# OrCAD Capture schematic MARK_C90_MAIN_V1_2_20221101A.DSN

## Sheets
1 PAGE08_USB_WIFI: size A3; title: MARK_C90_MAIN; rev: V1.2; note: PAGE08_USB-WIFI
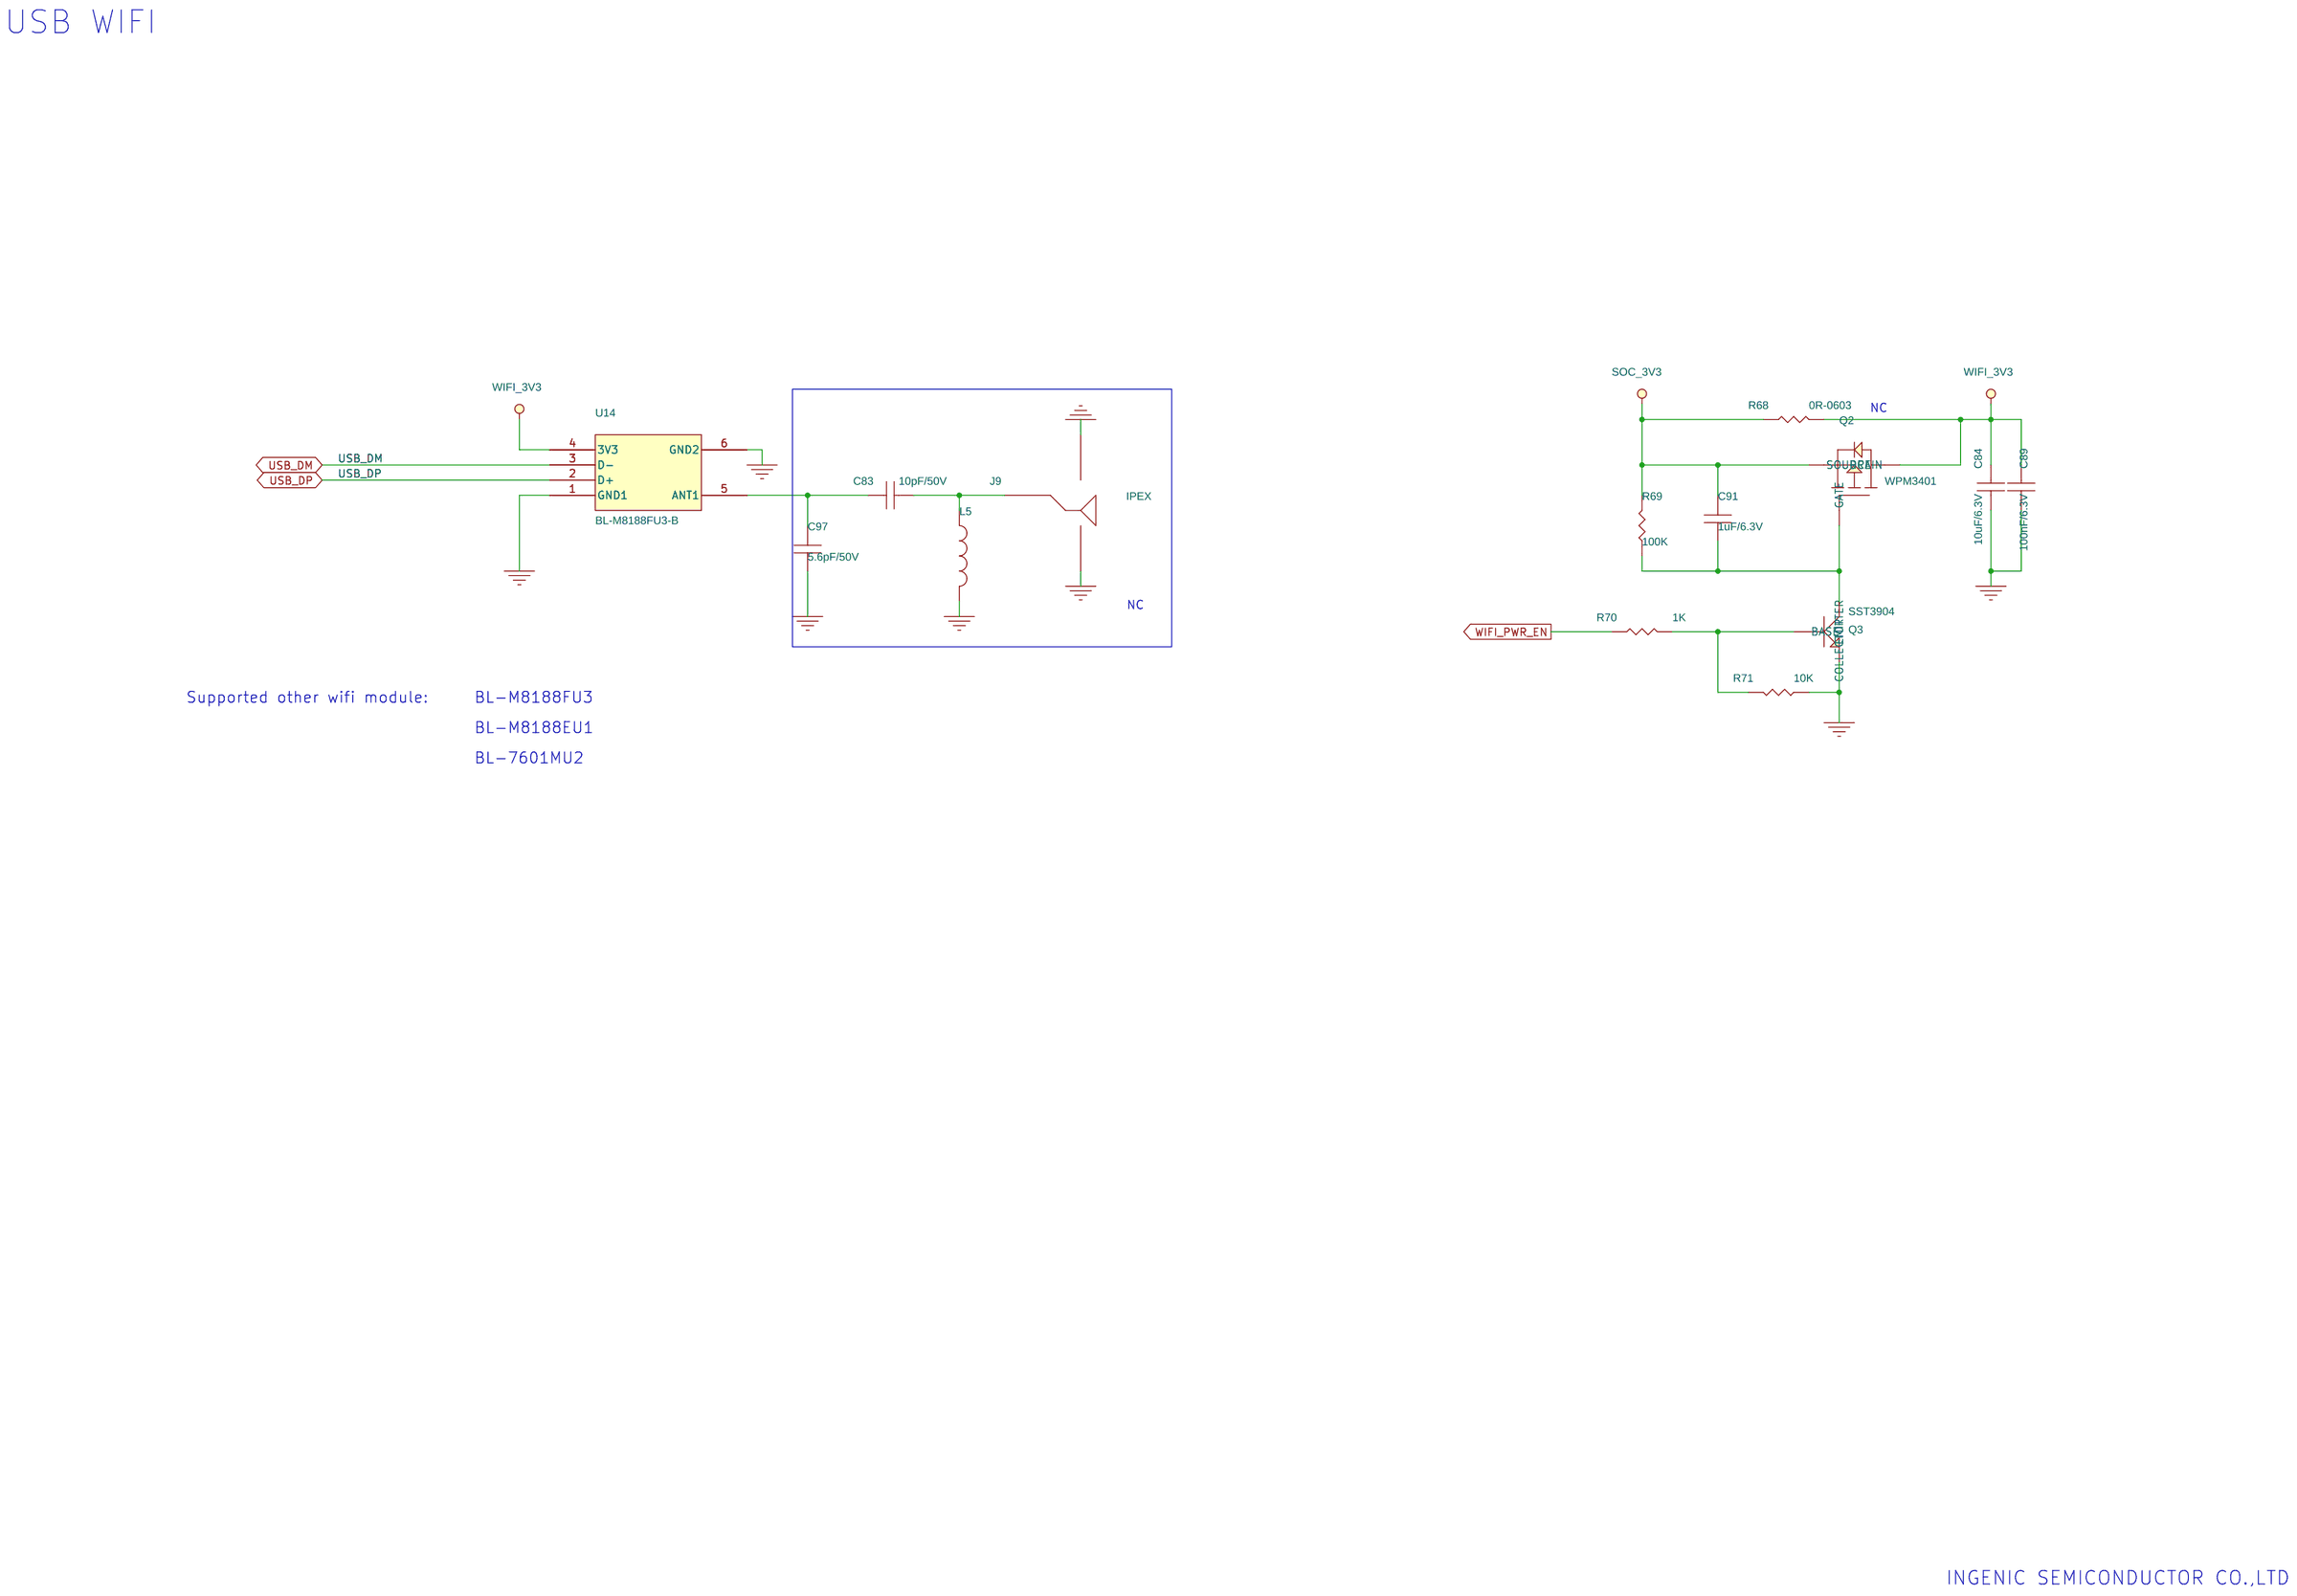
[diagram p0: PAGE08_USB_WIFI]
2 PAGE12_MOTOR_RST_LED: size A3; note: PAGE12_MOTOR_RST_LED
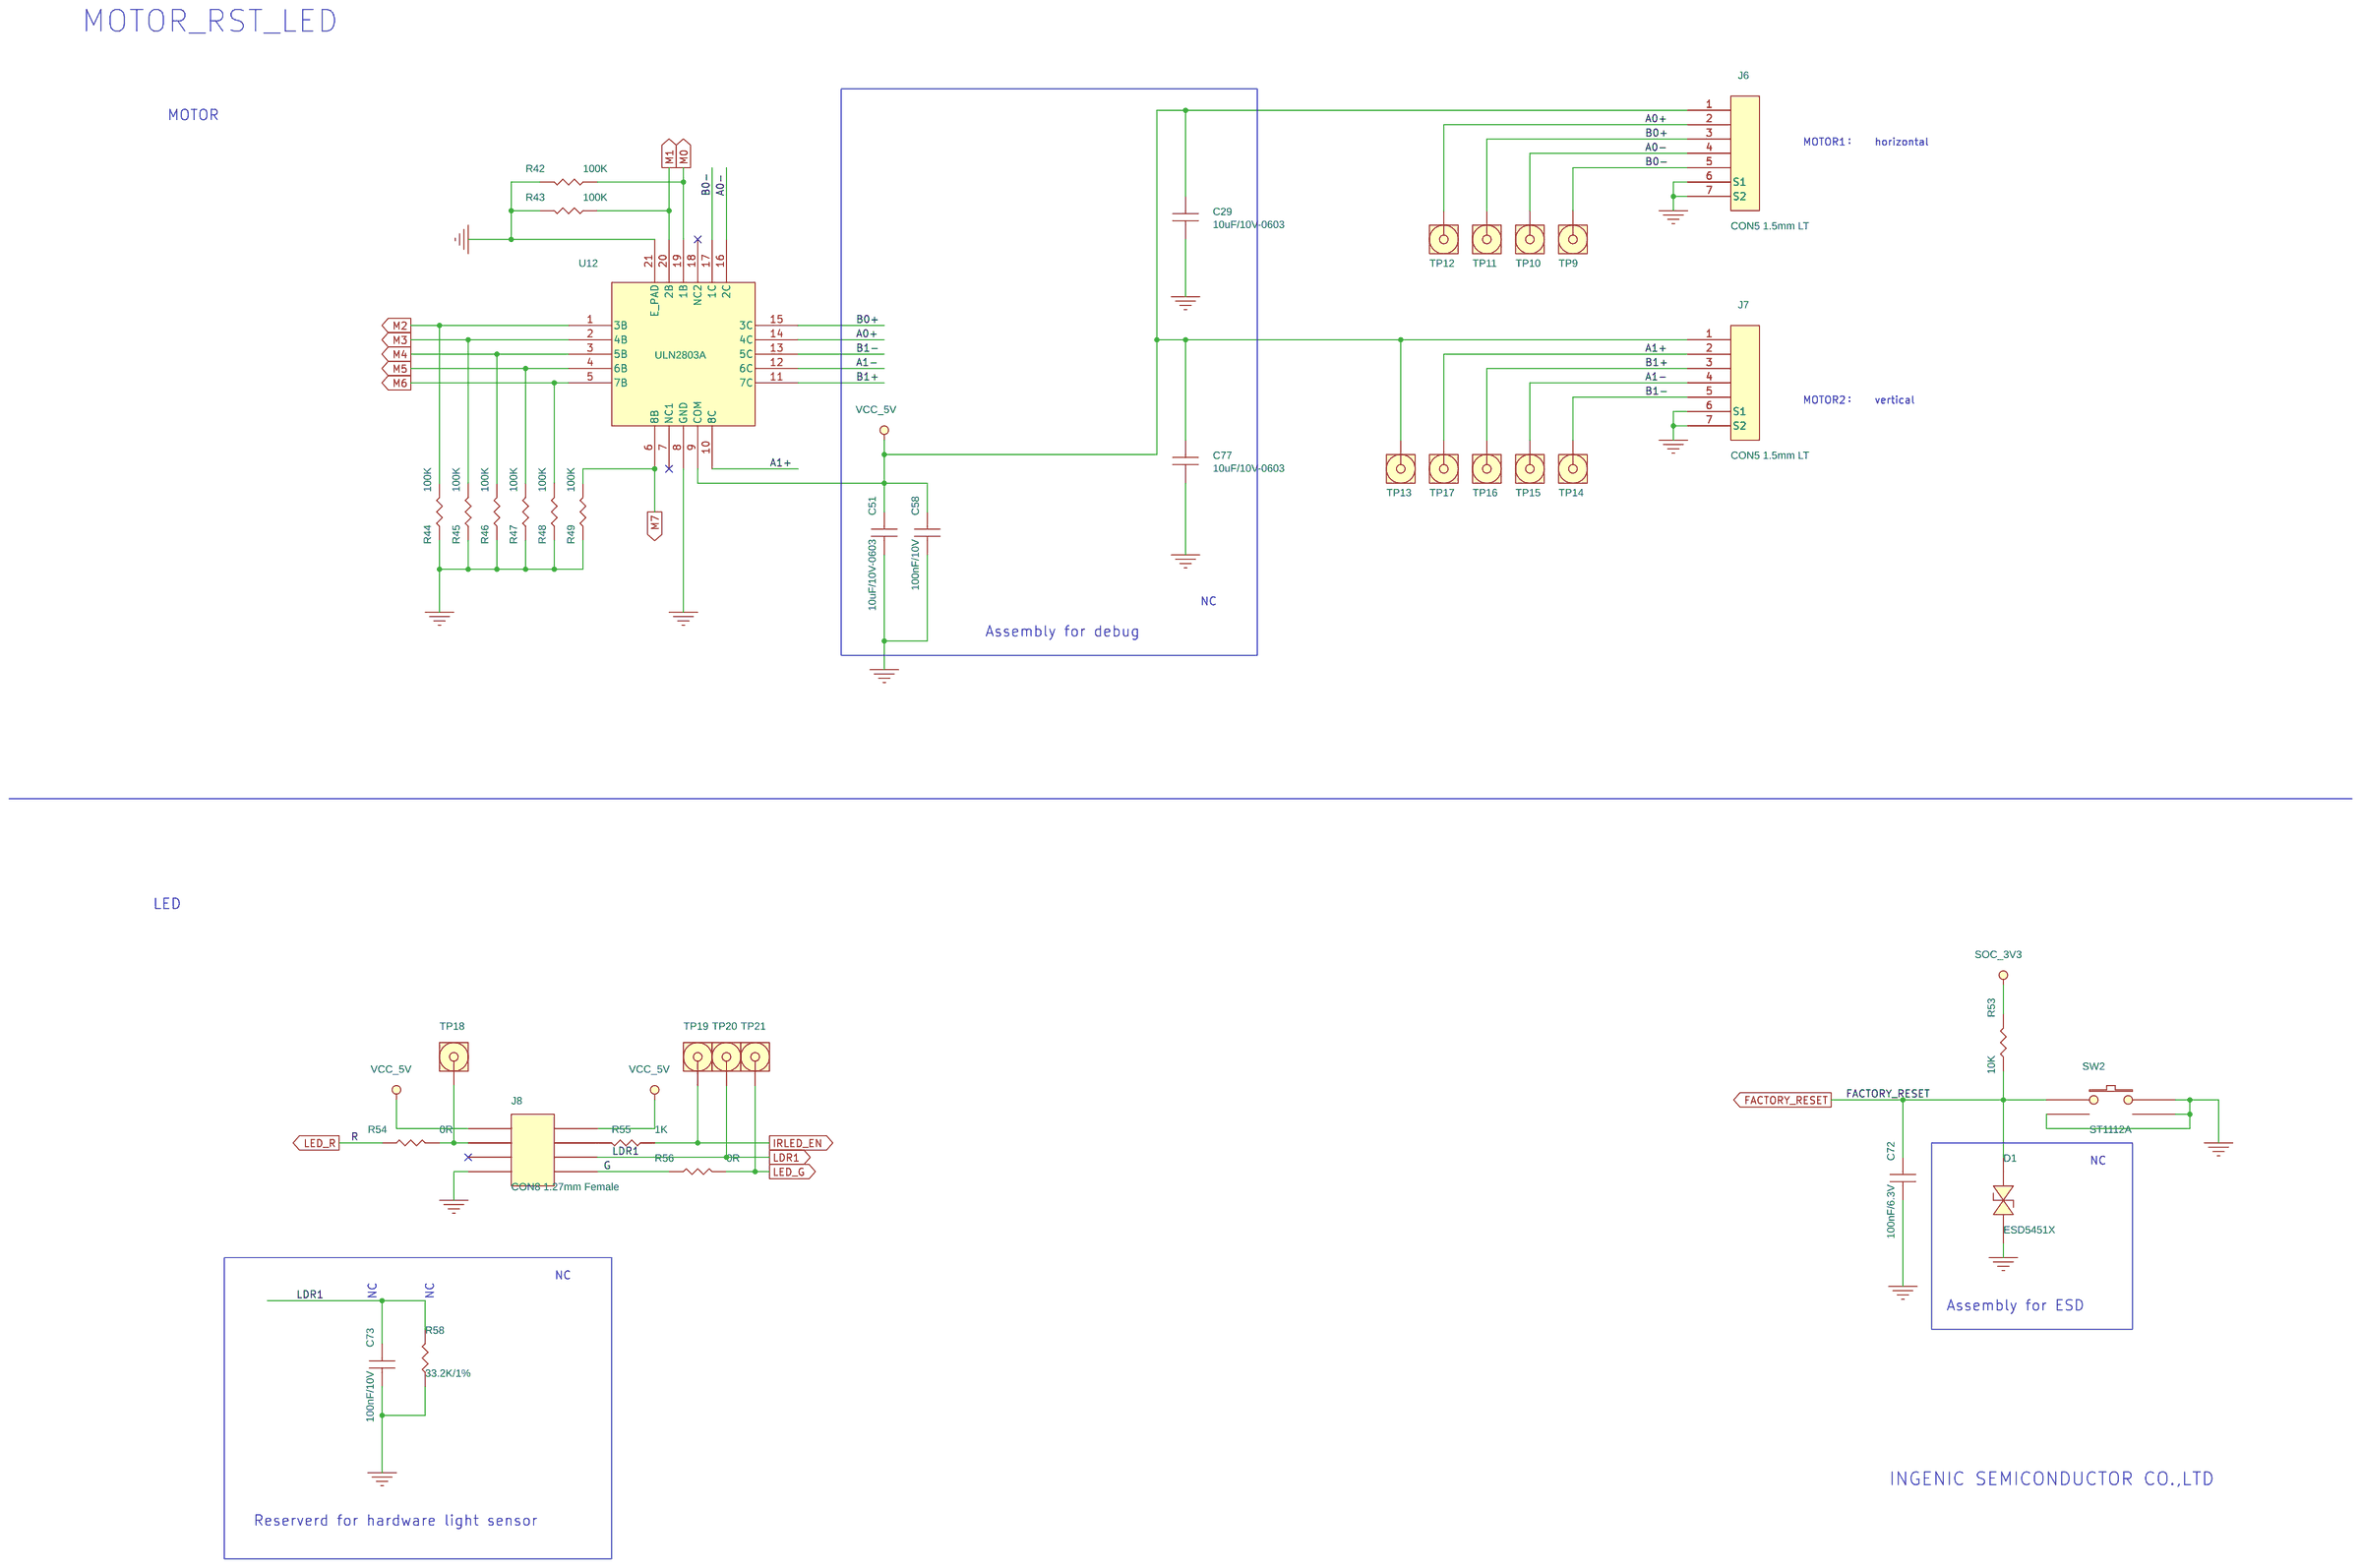
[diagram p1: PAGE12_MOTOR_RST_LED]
3 PAGE10_SENSOR: size A3; note: PAGE10_SENSOR
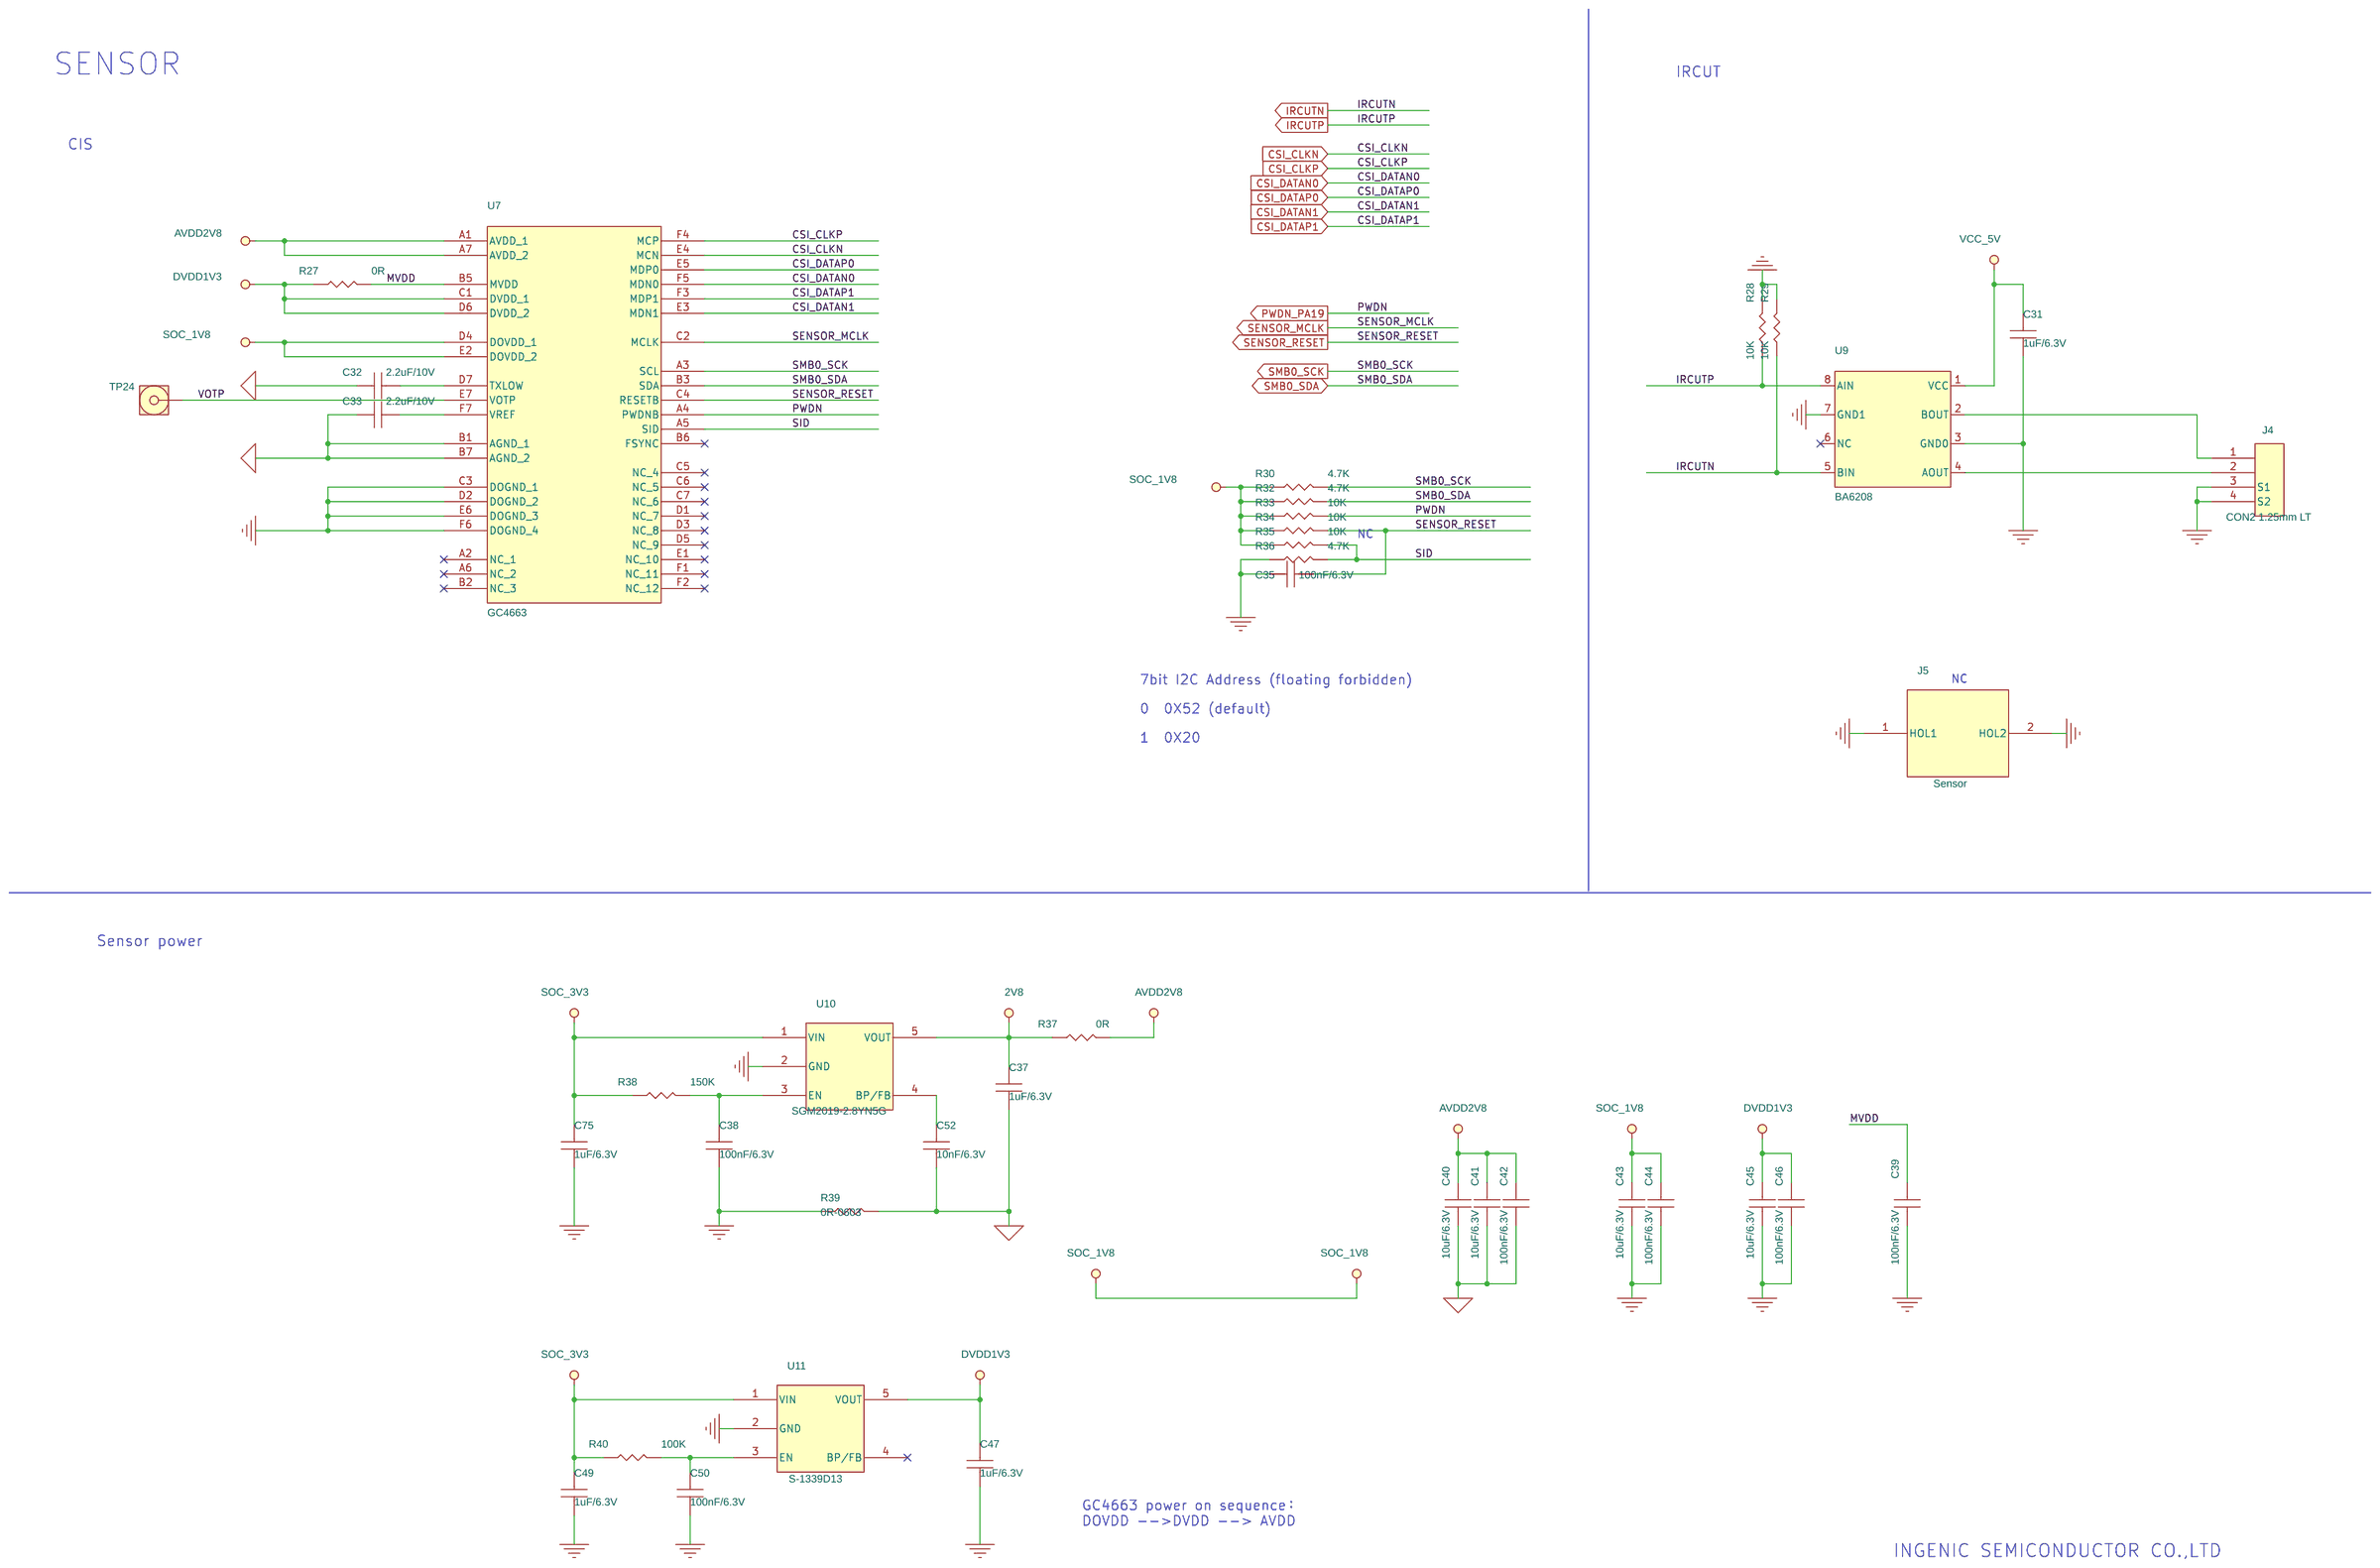
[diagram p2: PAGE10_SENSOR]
4 PAGE01_COVER
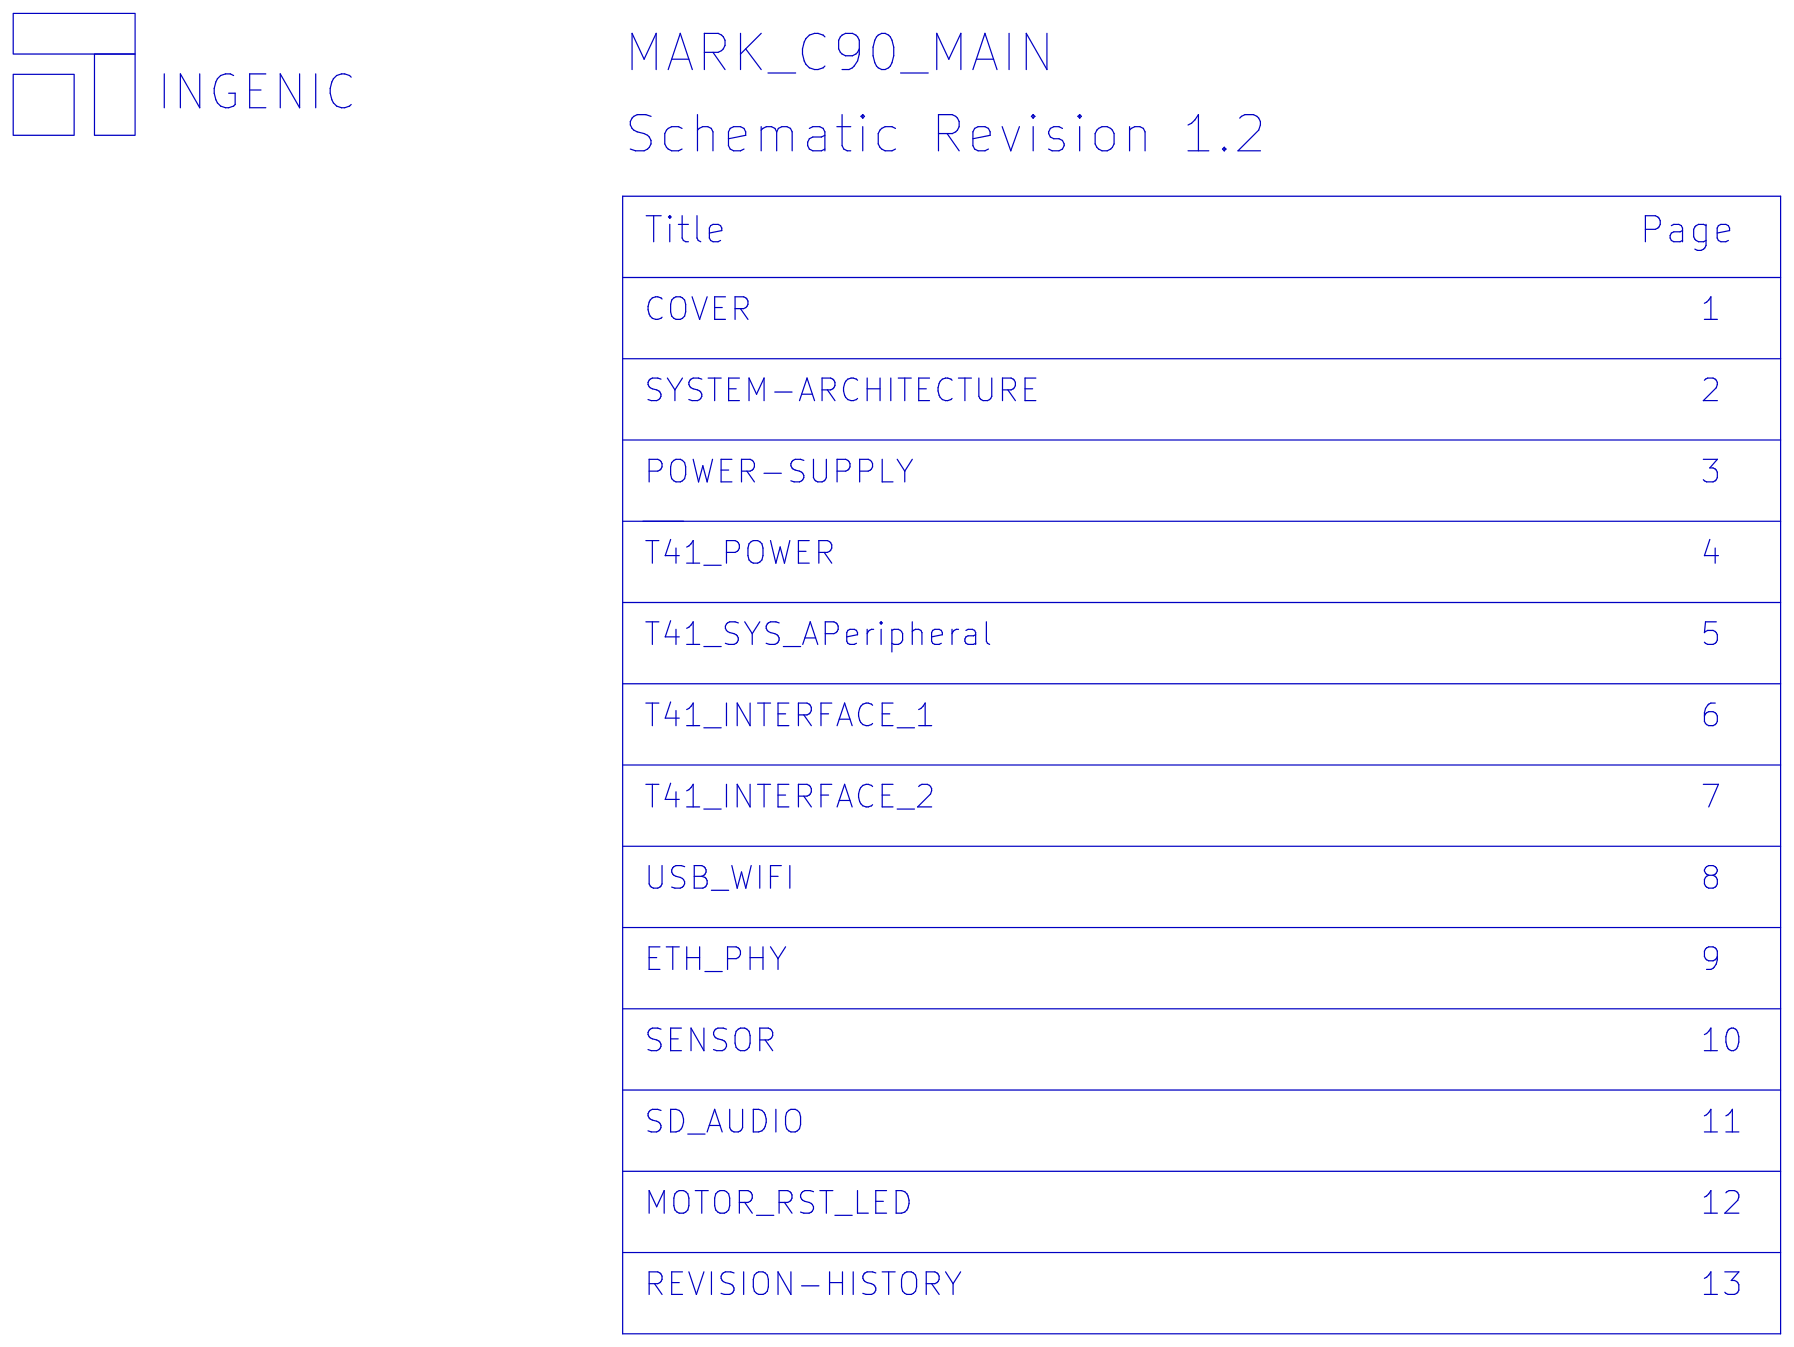
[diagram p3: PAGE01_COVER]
5 PAGE02_SYSTEM-ARCHITECT
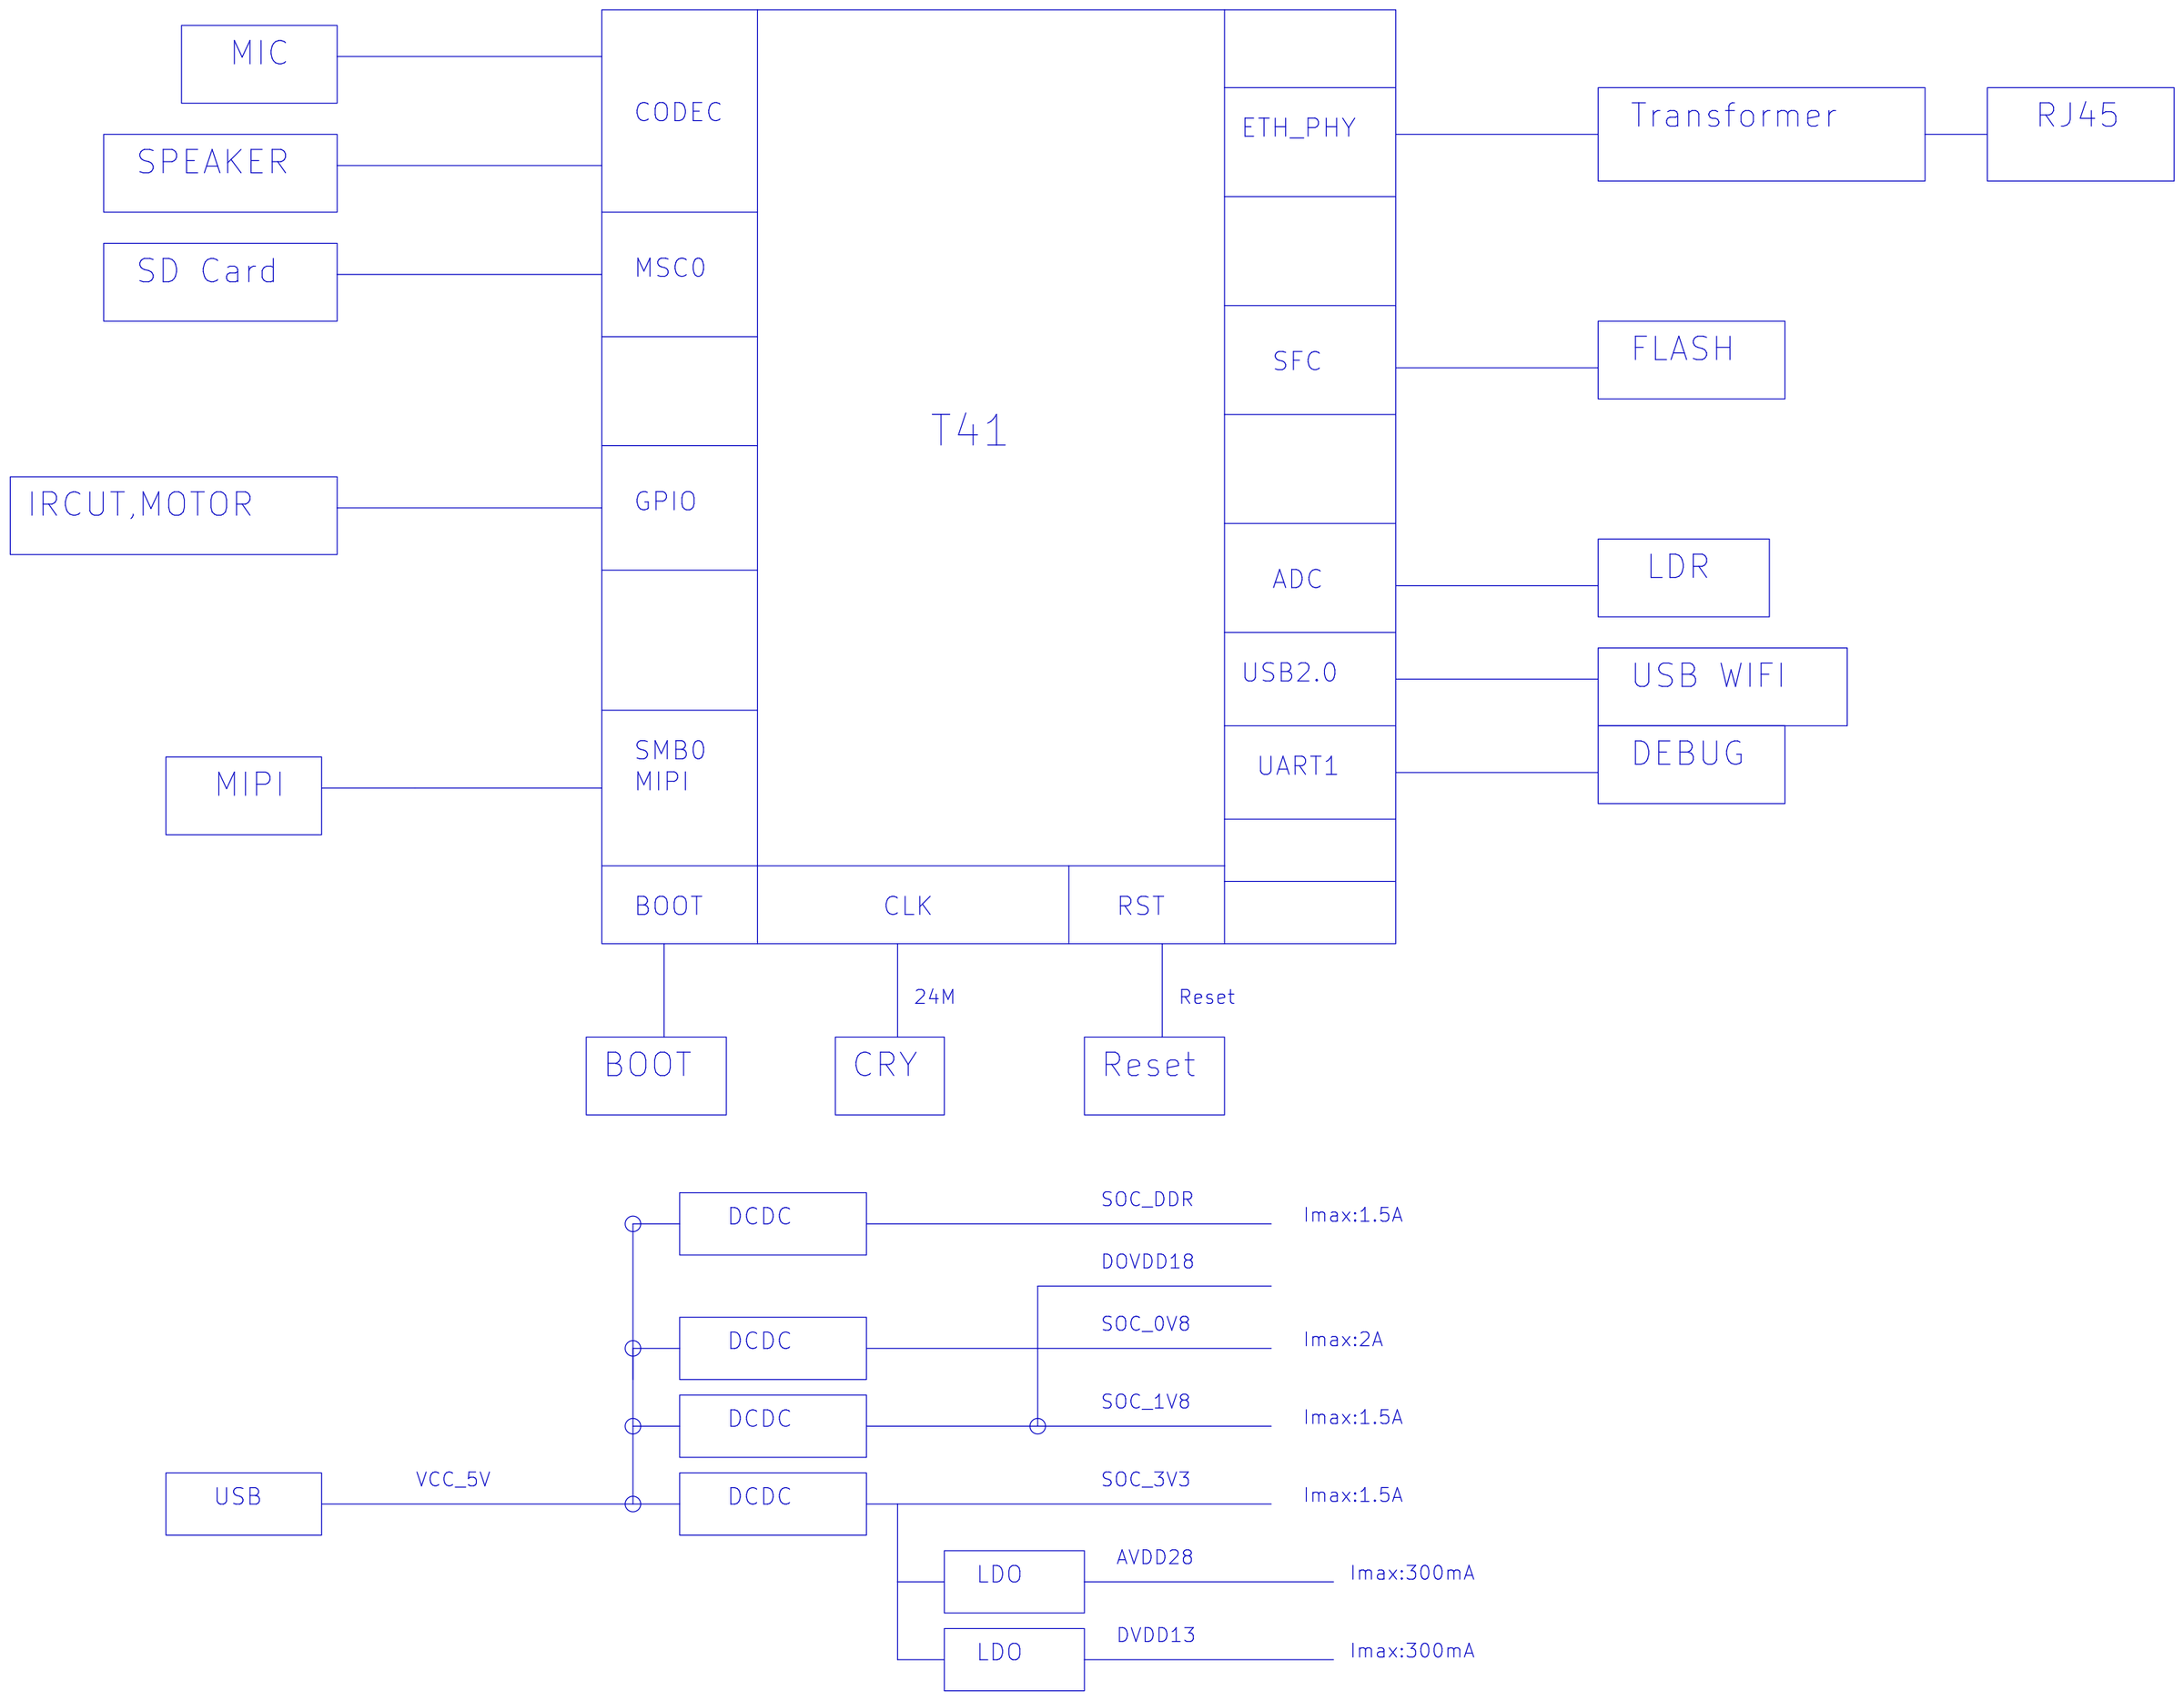
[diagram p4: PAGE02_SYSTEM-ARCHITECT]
6 PAGE03_POWER-SUPPLY: size A3
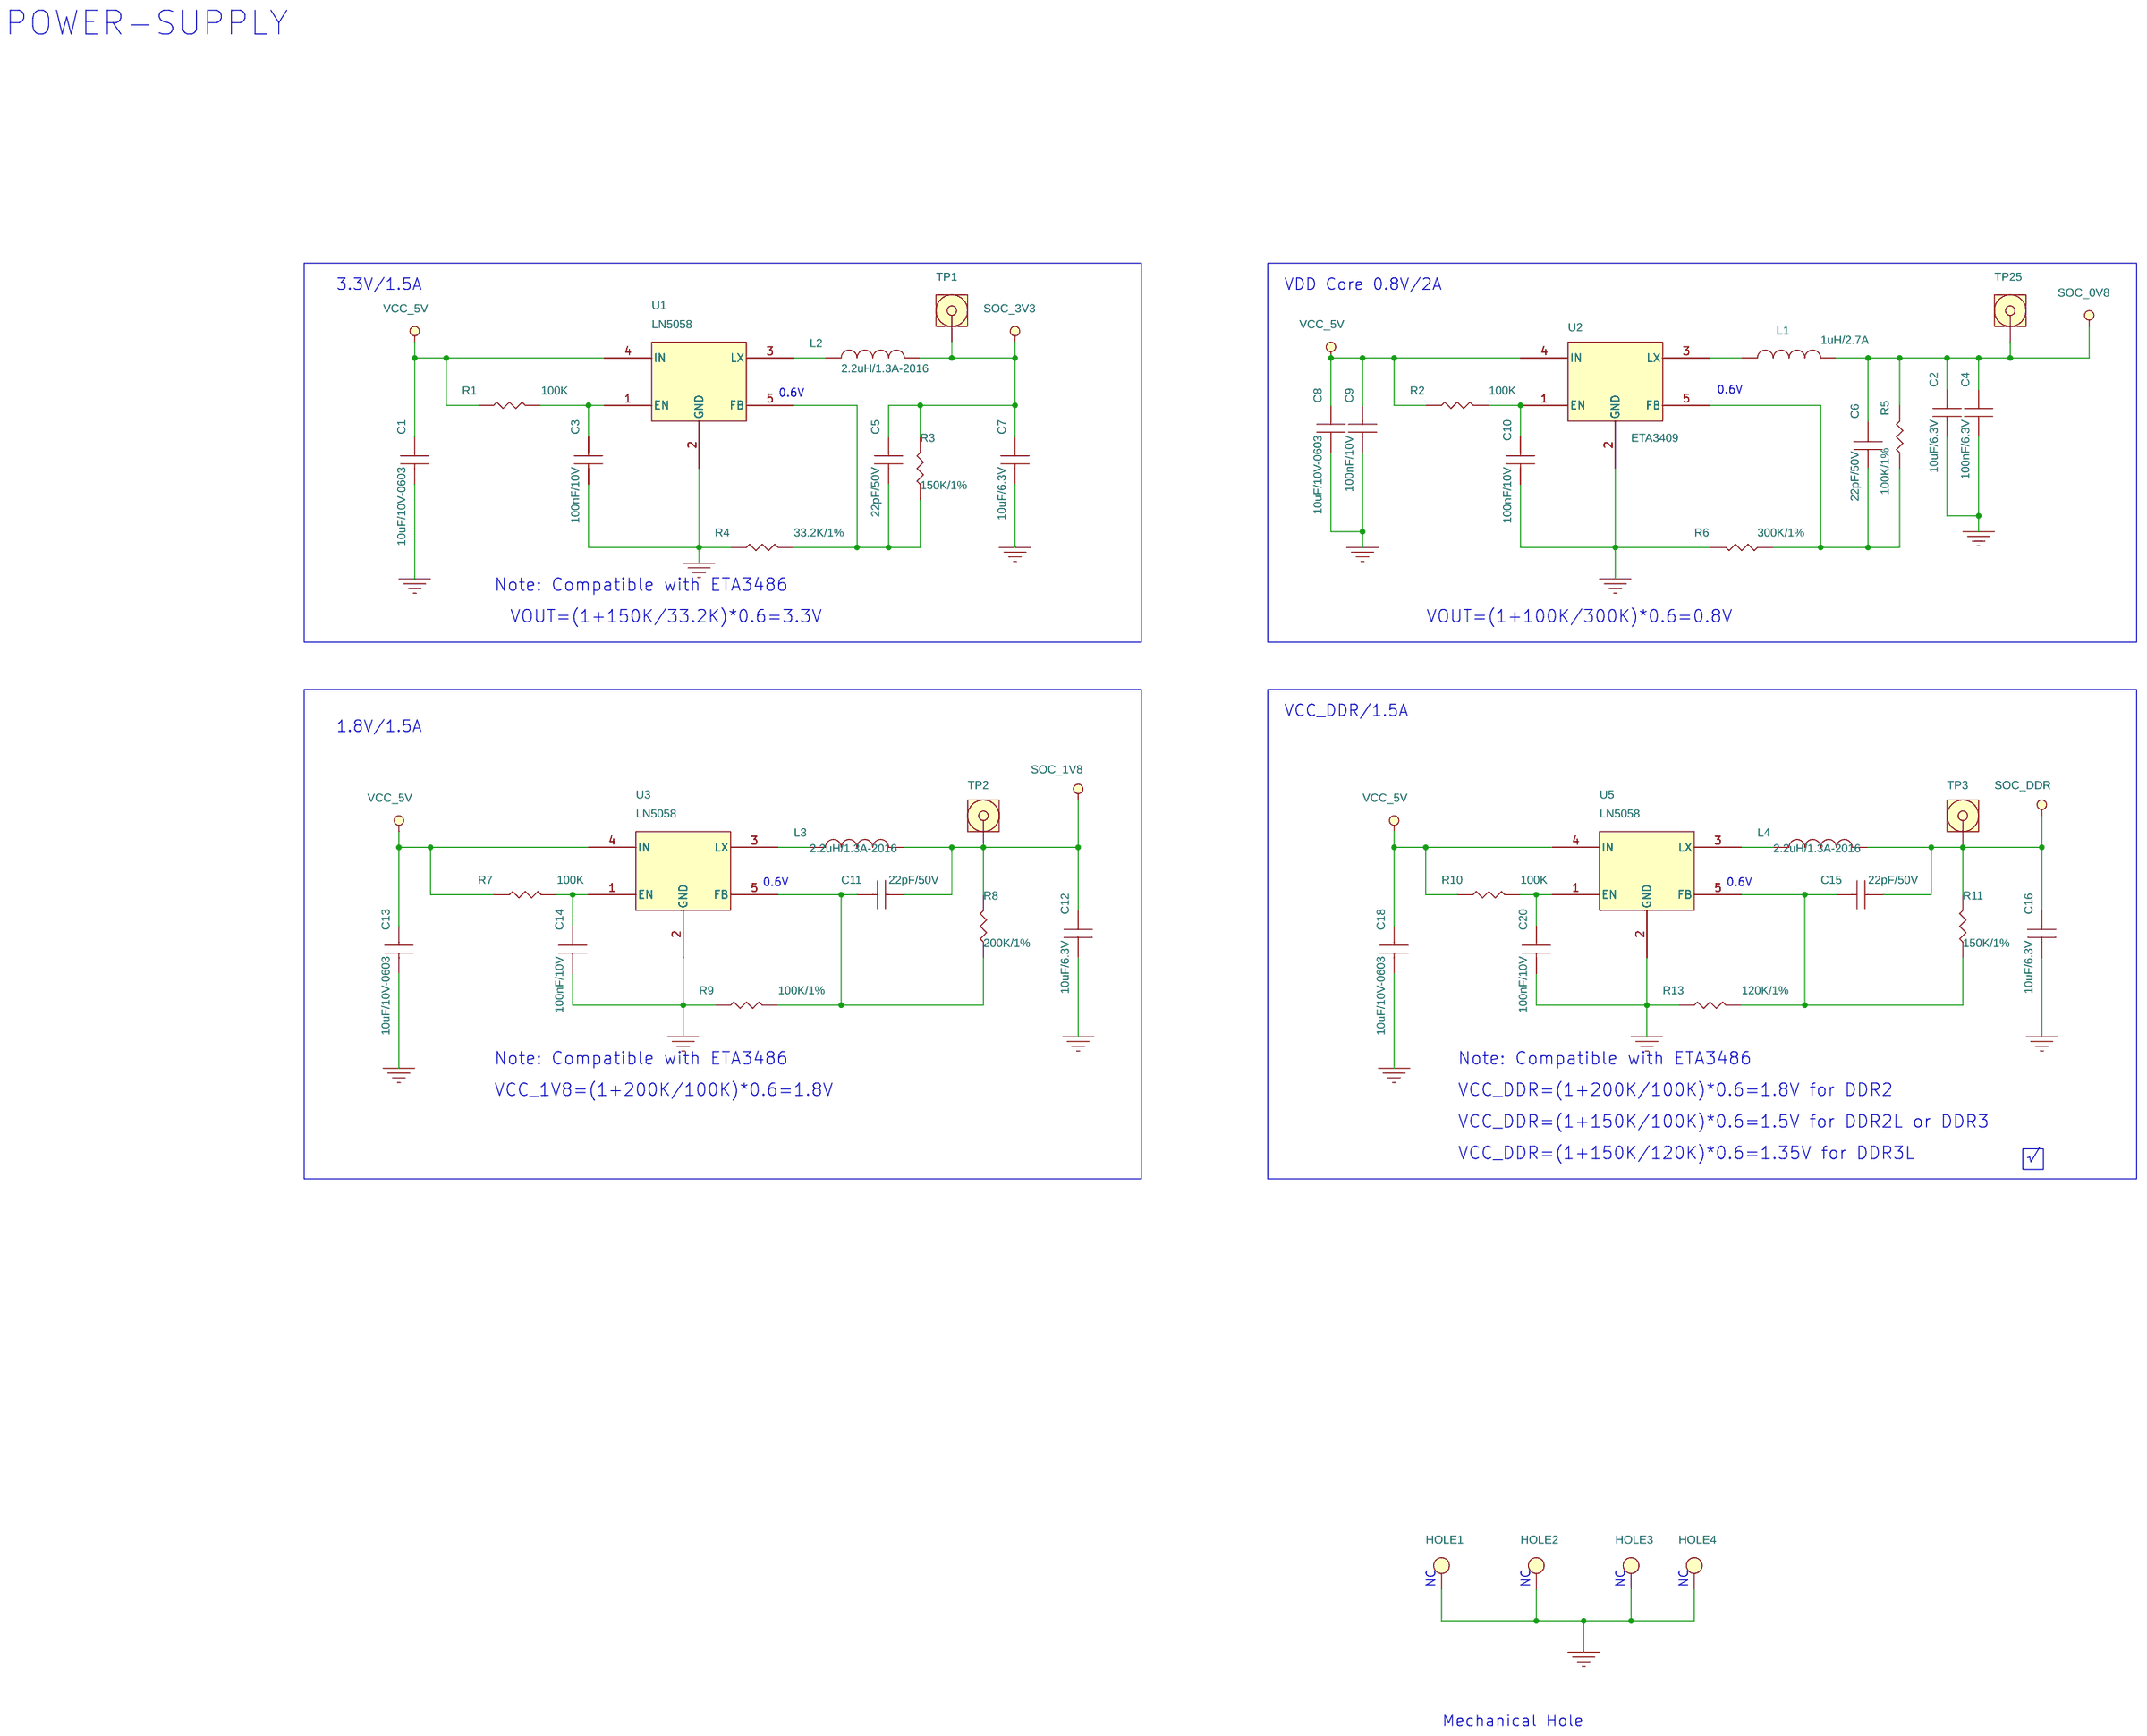
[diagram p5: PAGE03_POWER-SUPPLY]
7 PAGE04_T41_POWER: size A3
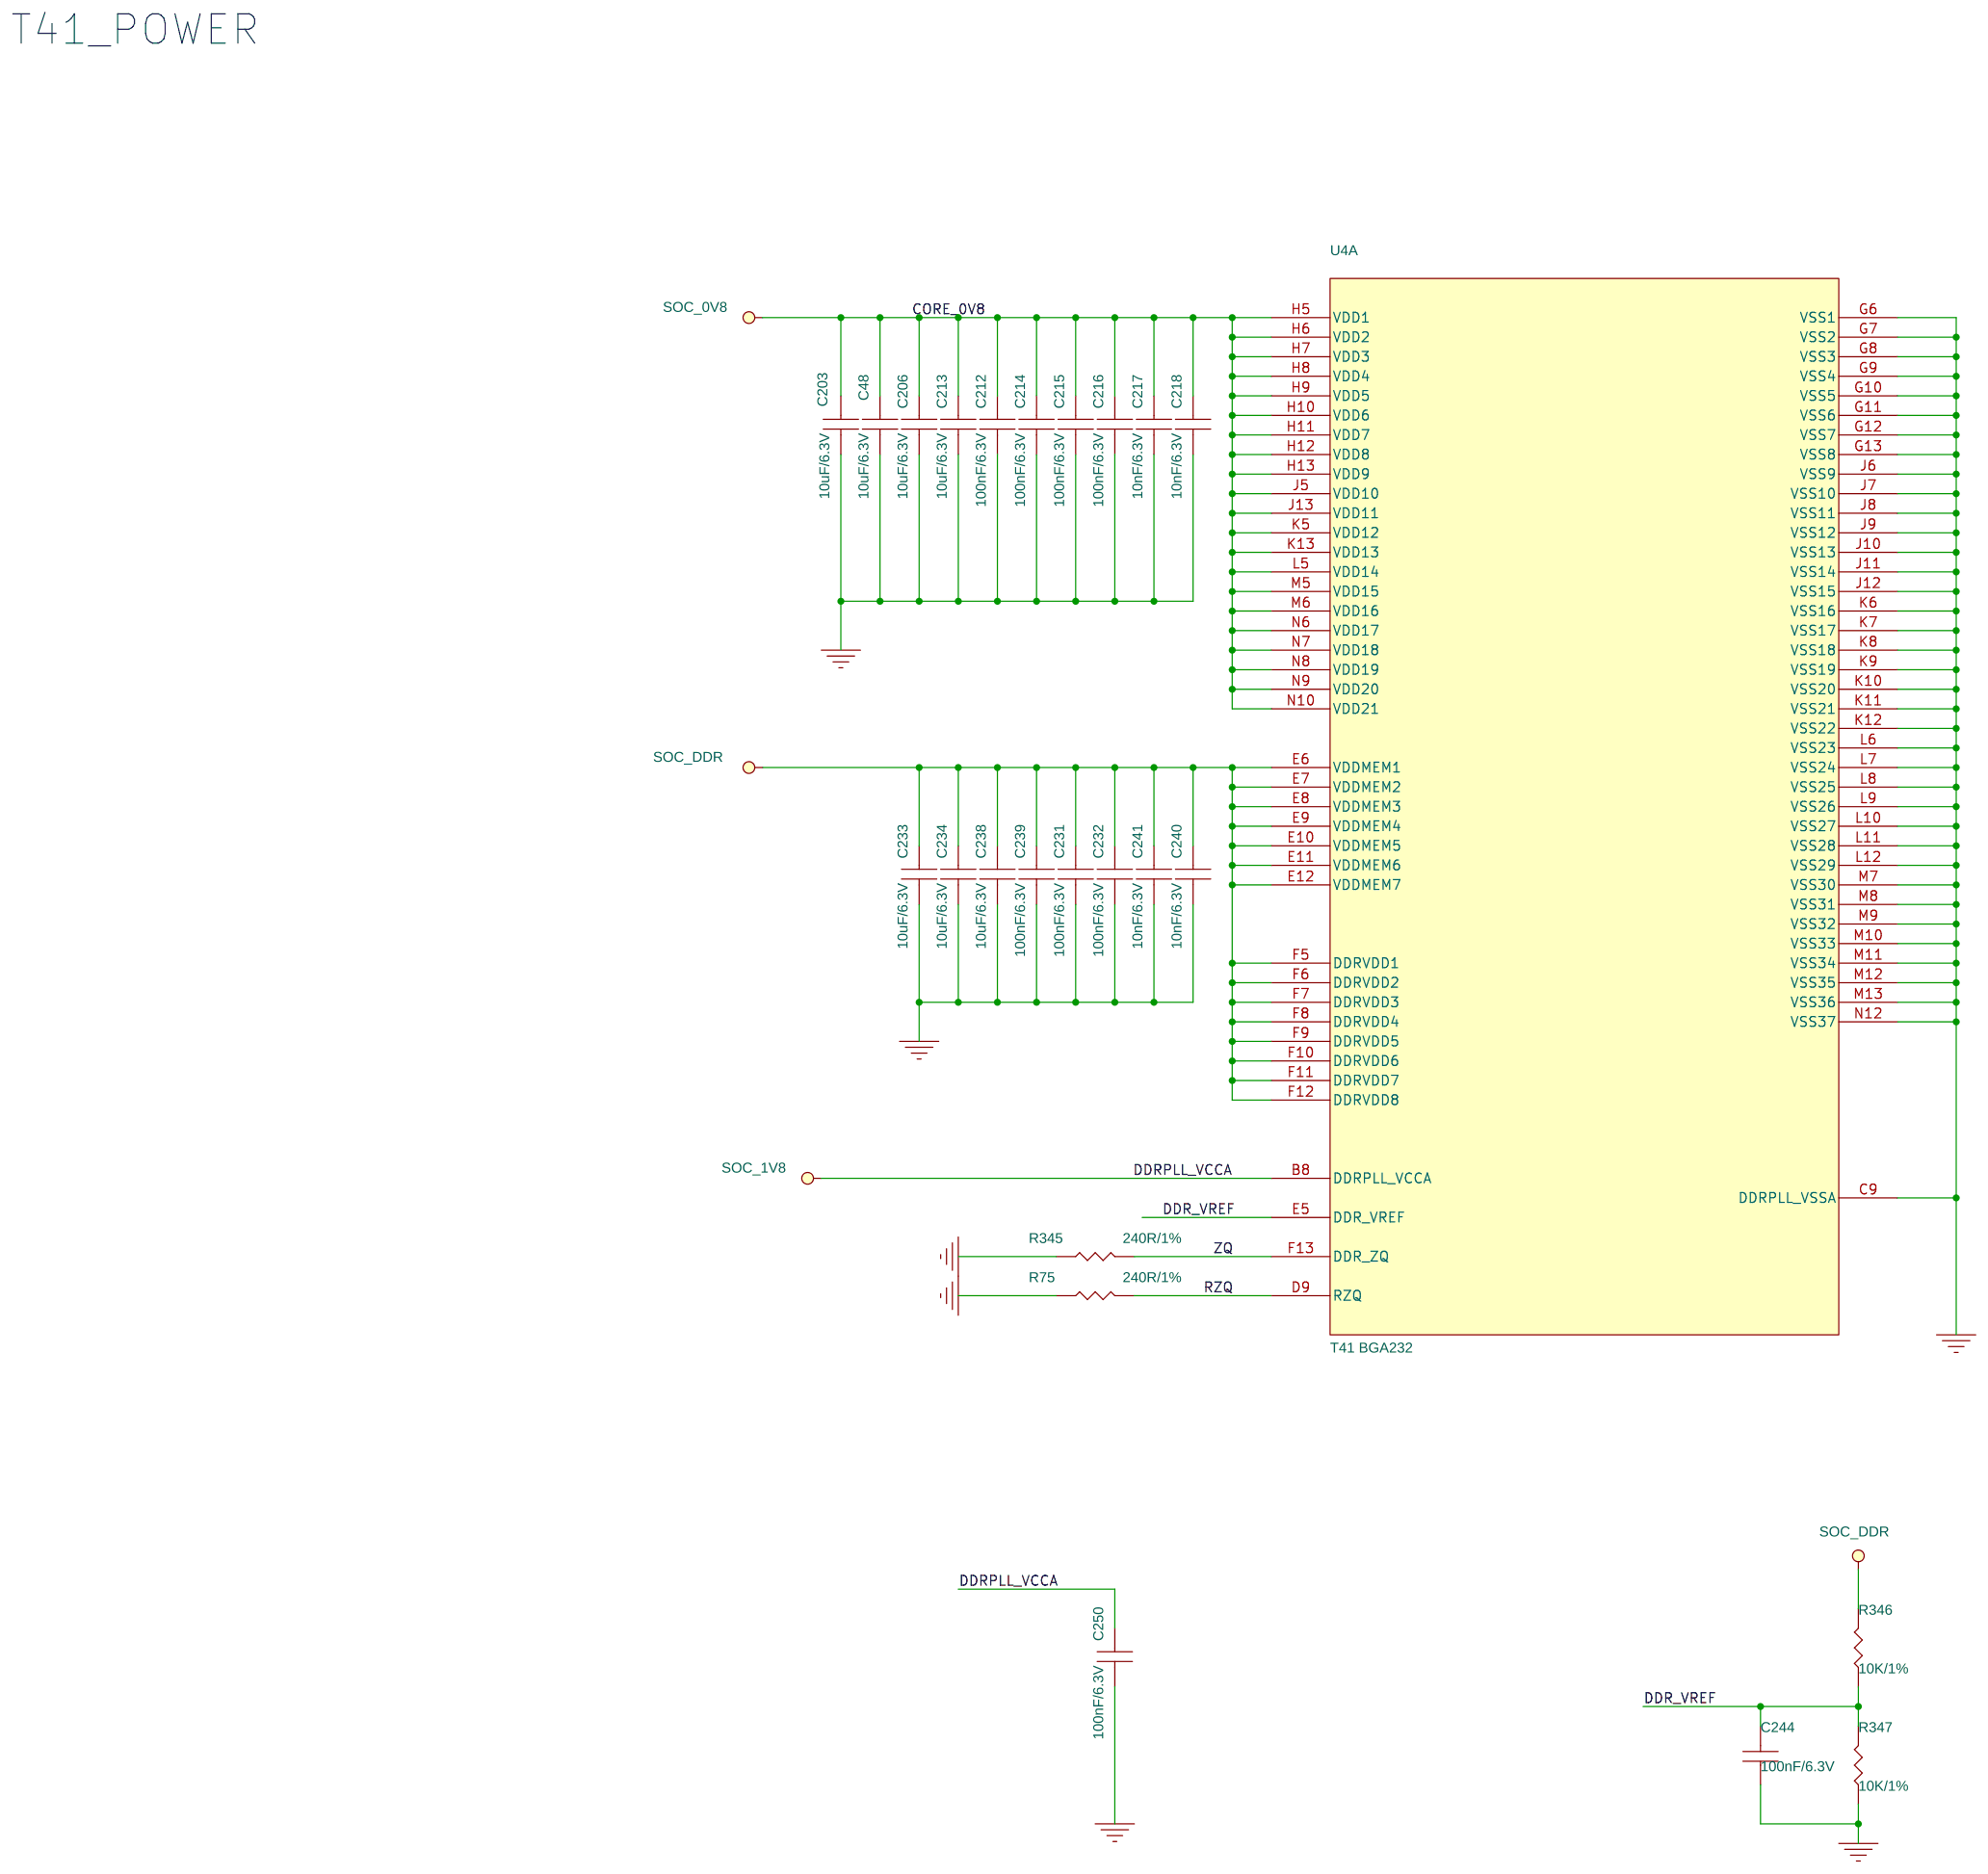
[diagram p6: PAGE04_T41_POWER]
8 PAGE05_T41_SYS_APeripheral: size A3
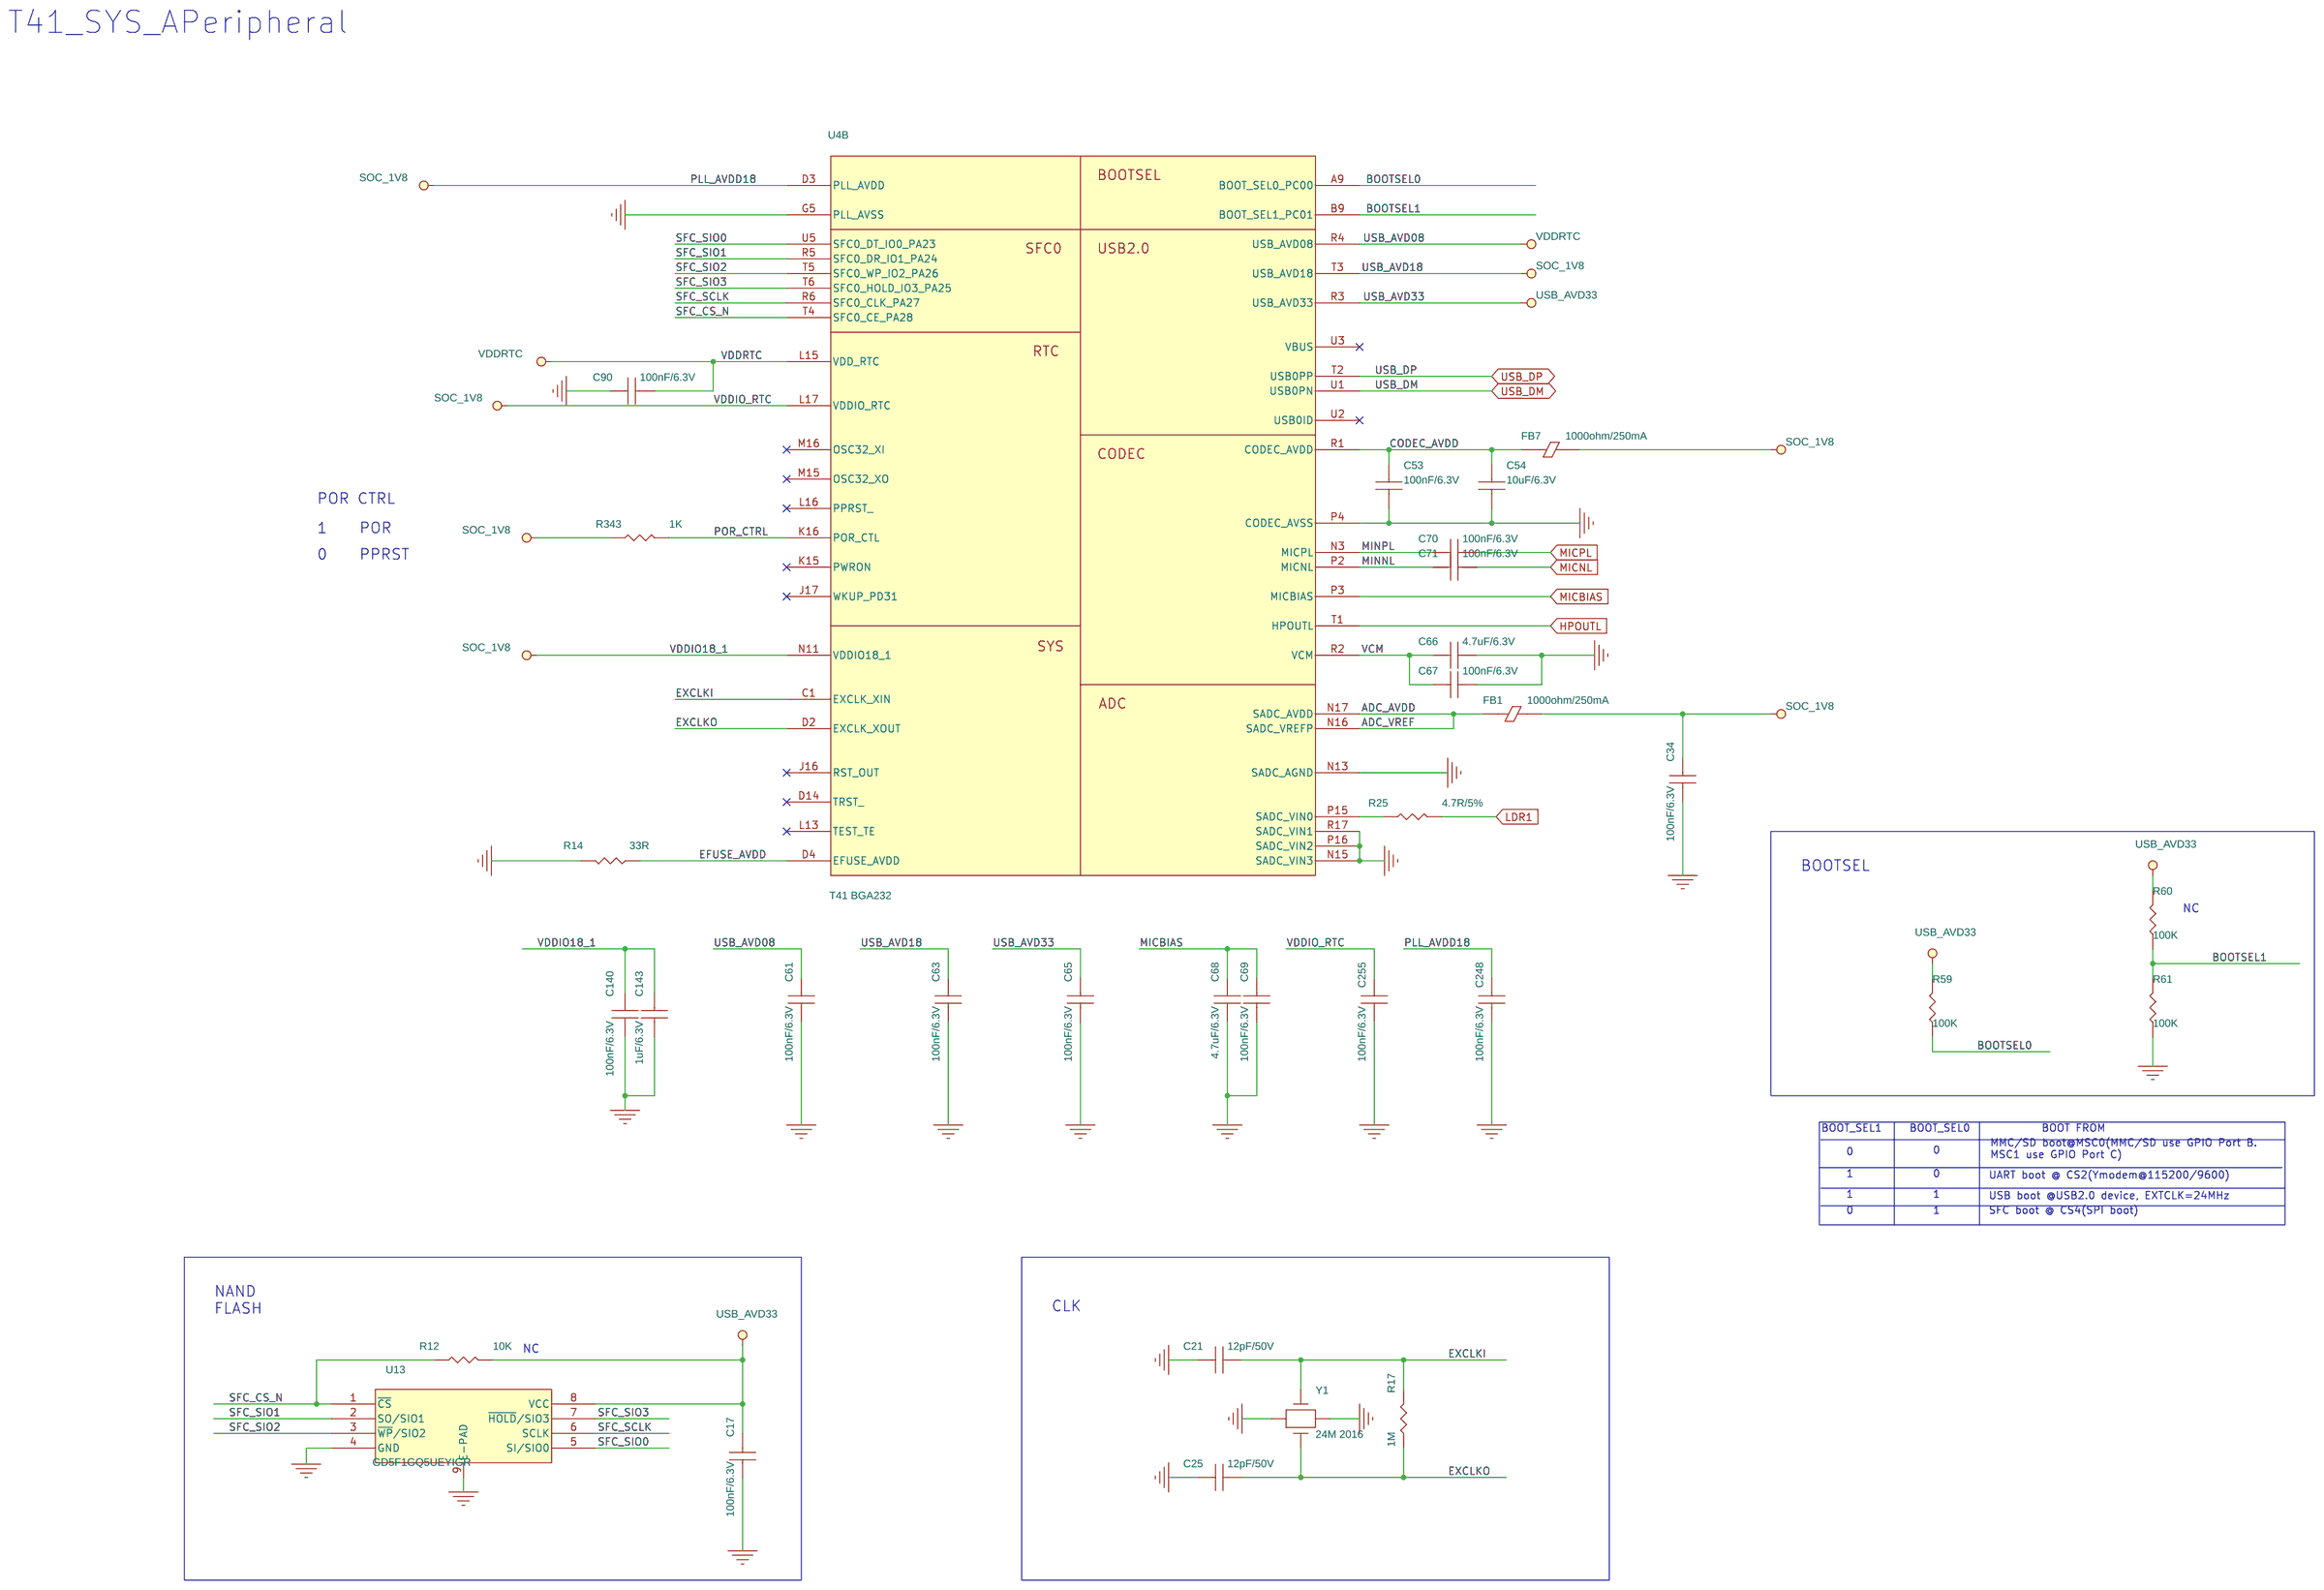
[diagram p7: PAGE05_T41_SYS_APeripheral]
9 PAGE06_T41_INTERFACE_1: size A3
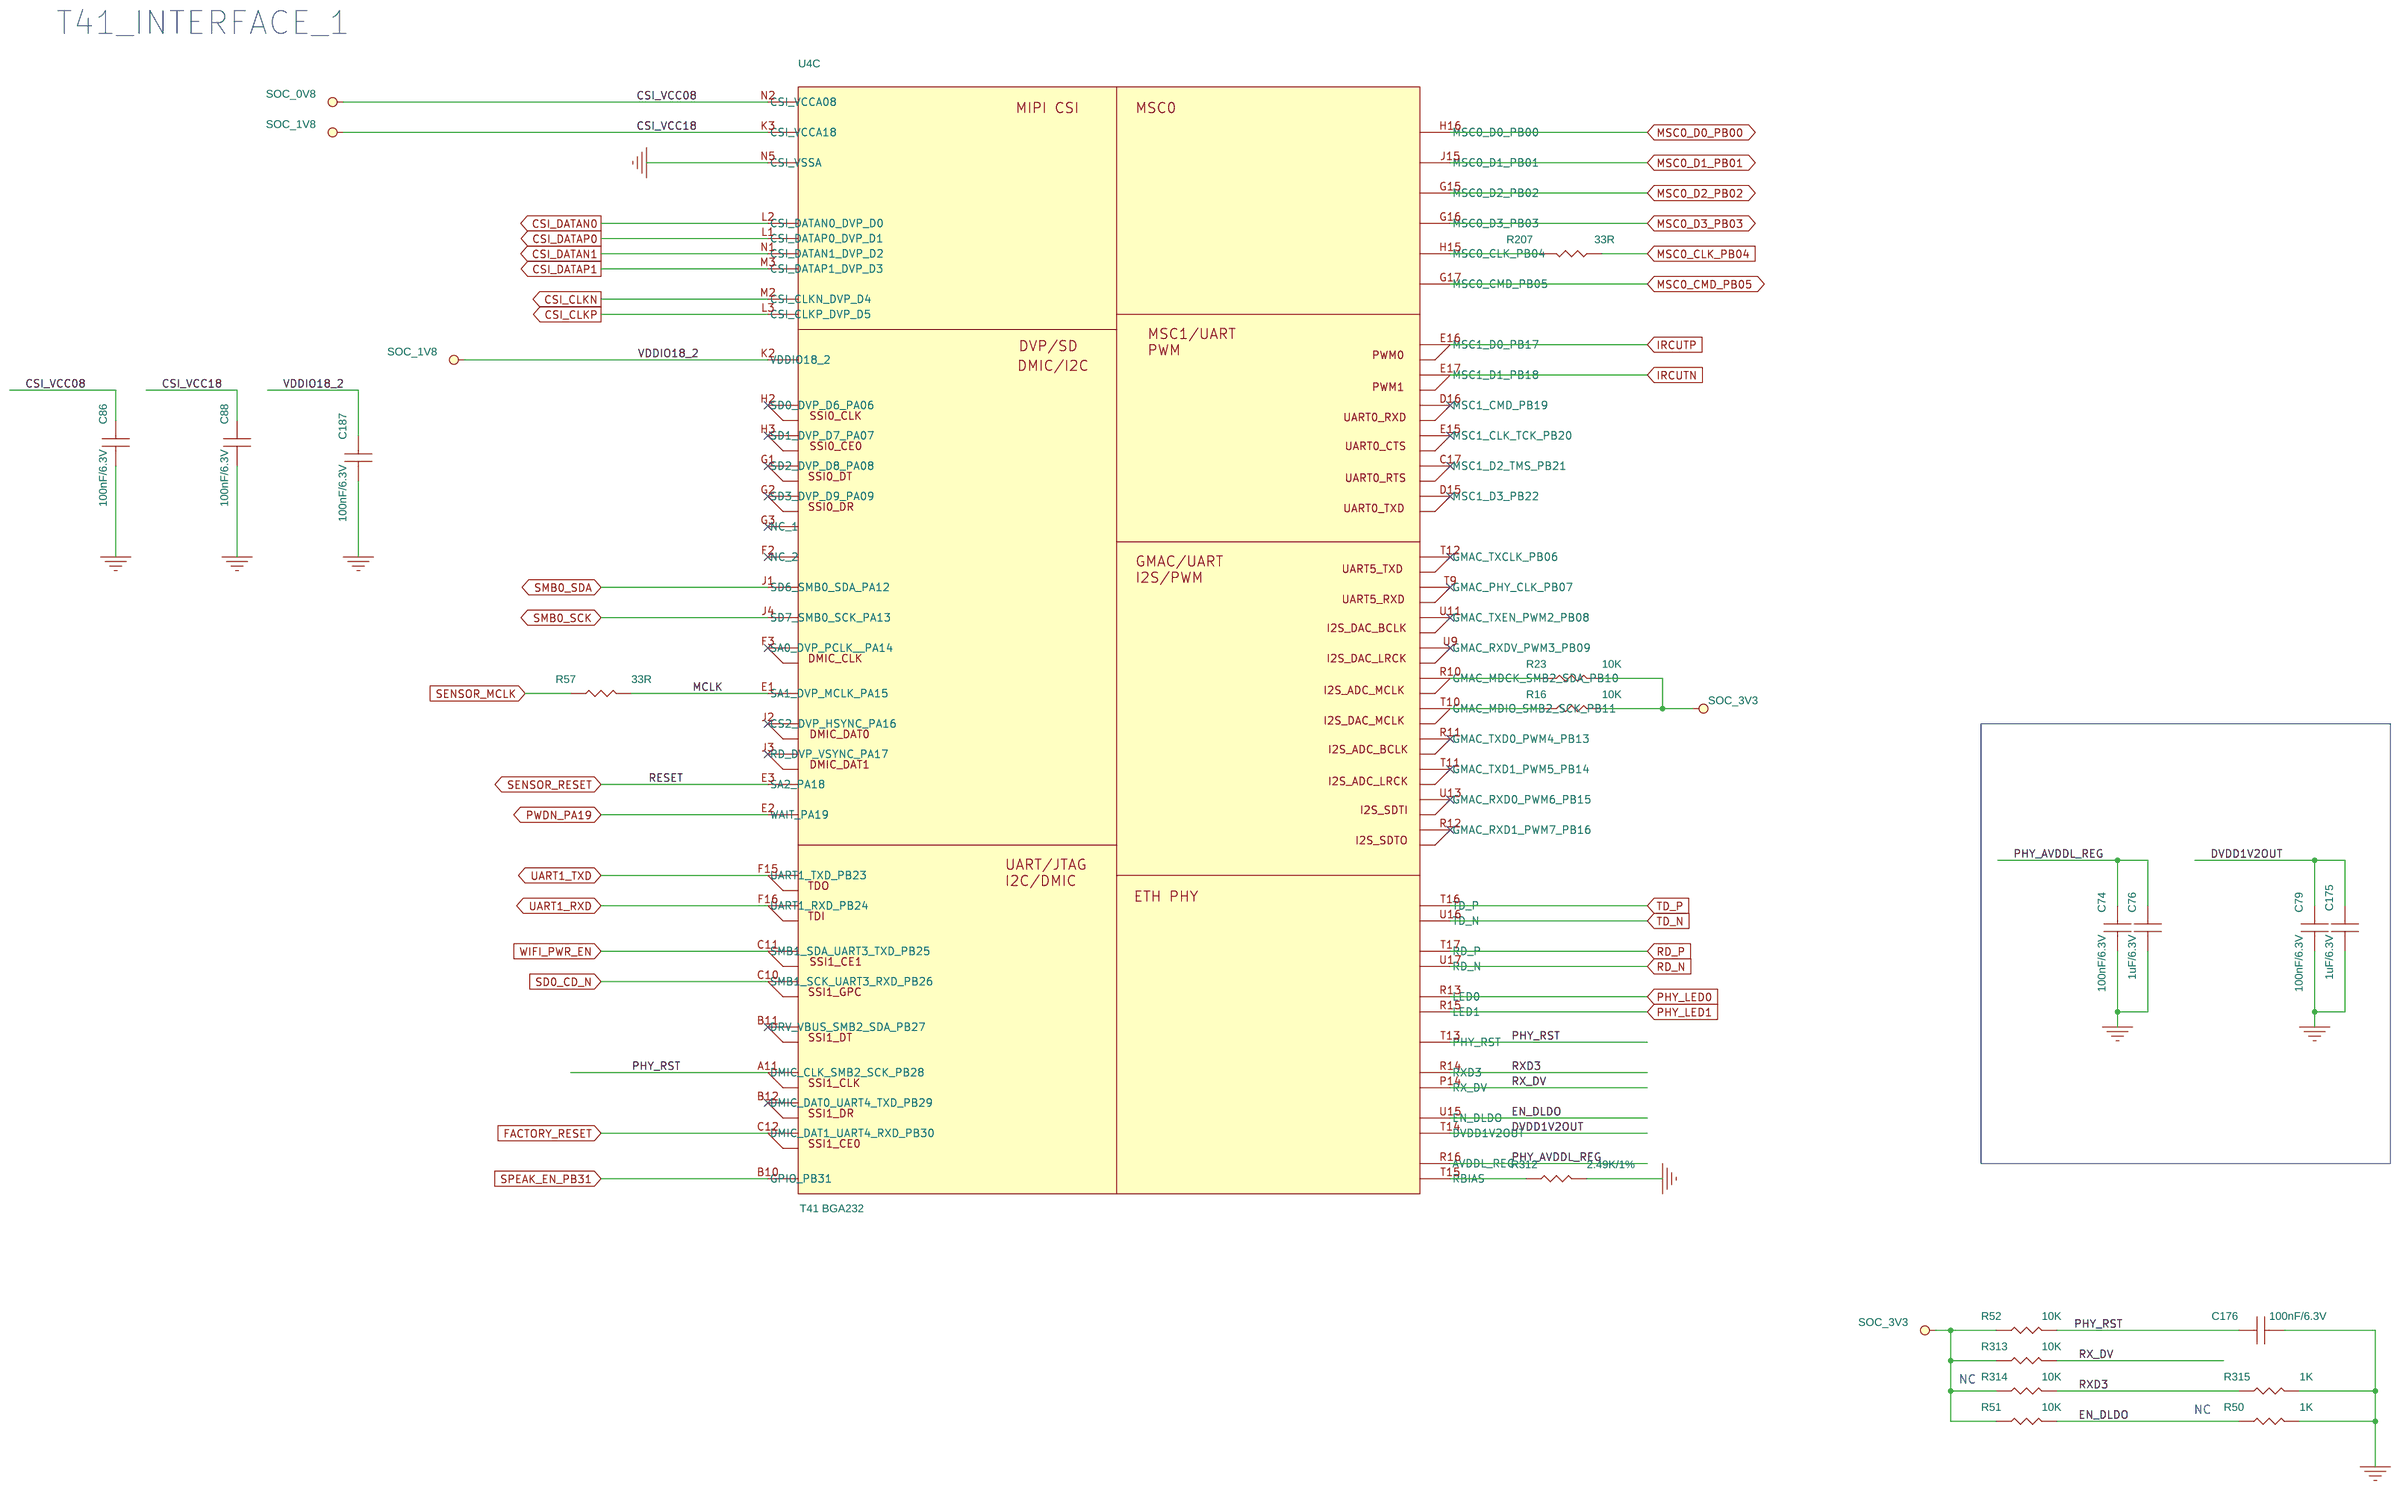
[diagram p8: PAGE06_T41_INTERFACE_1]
10 PAGE07_T41_INTERFACE_2: size A3
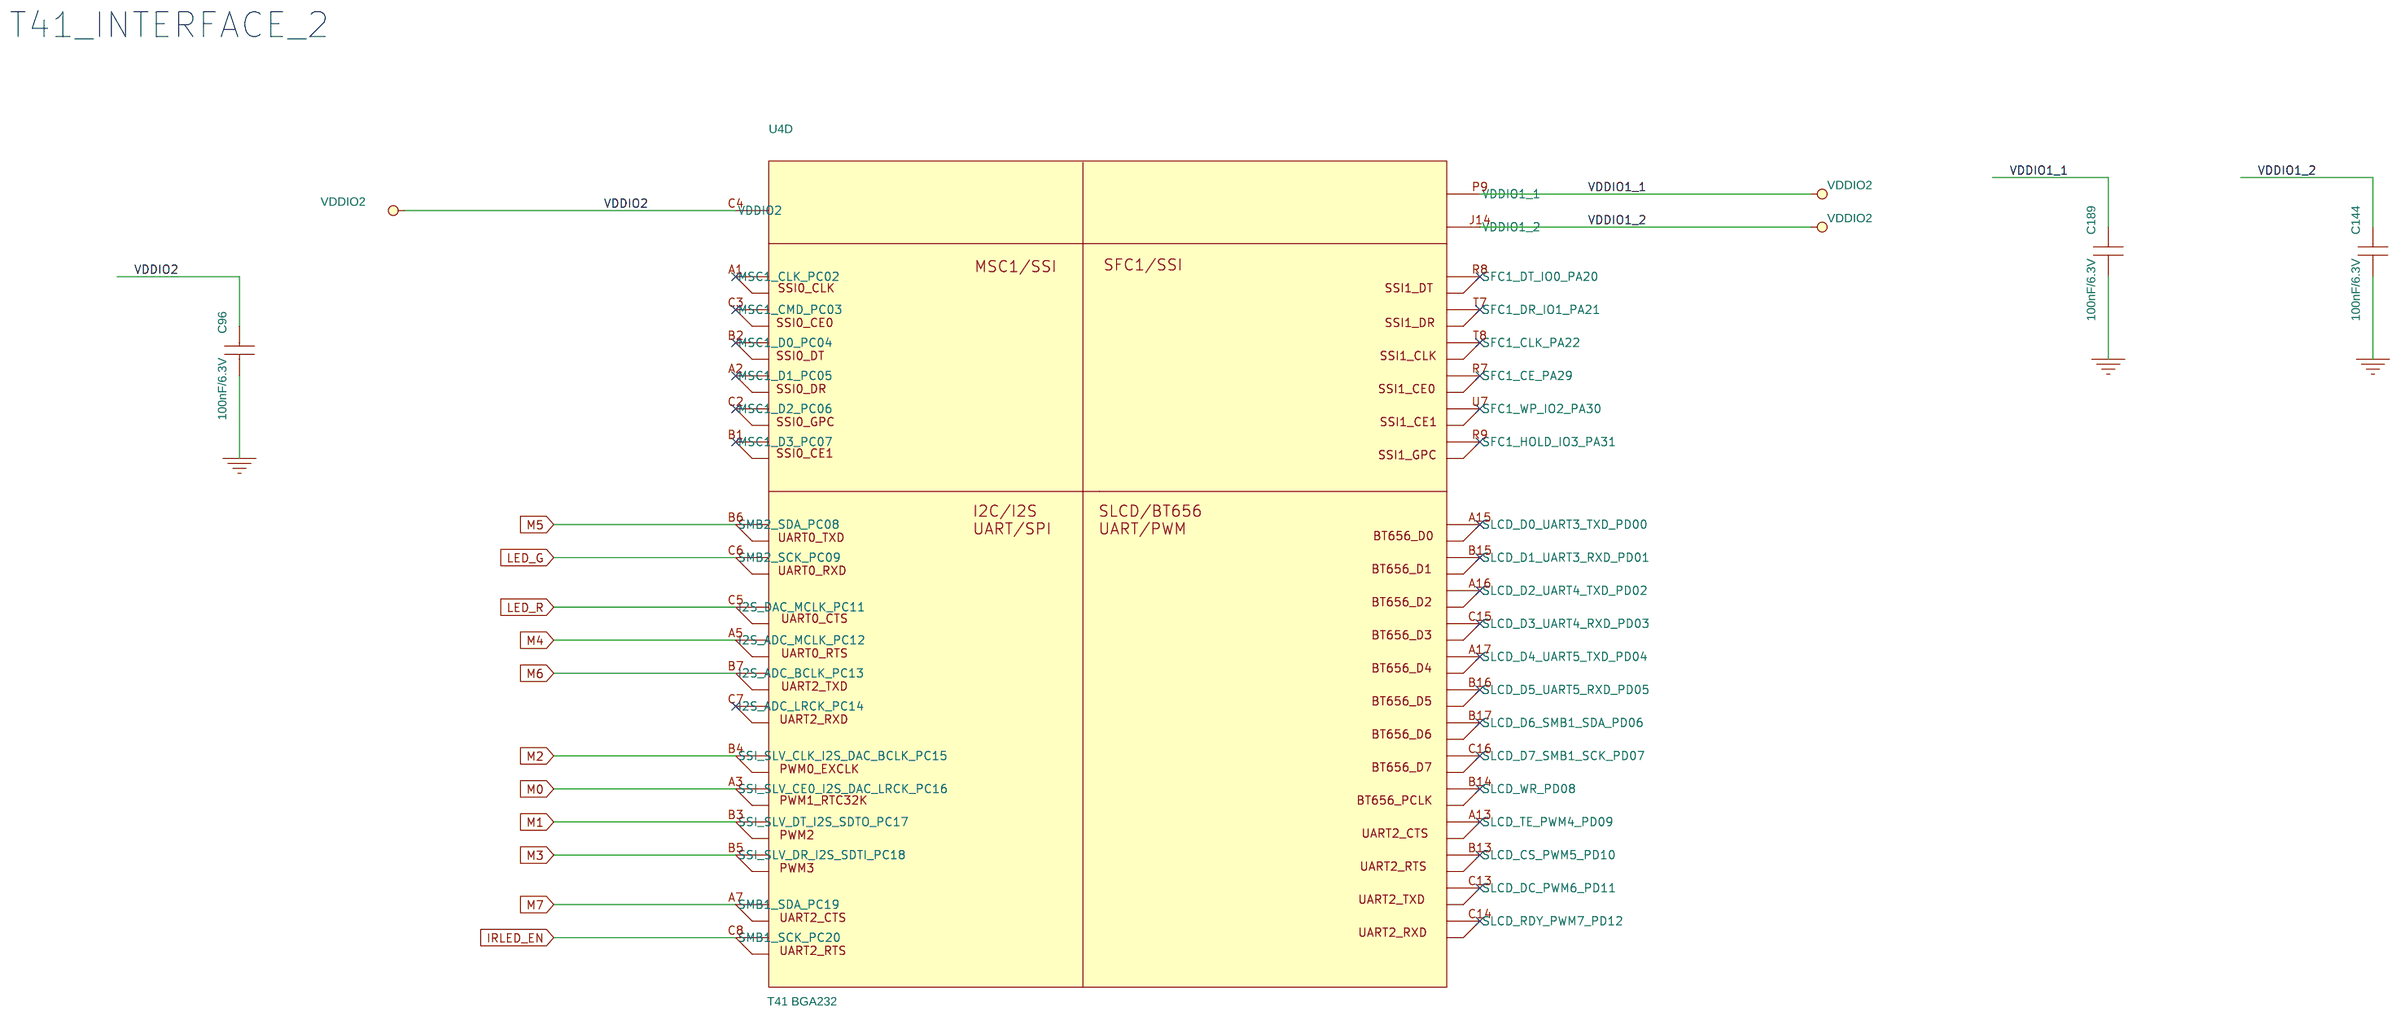
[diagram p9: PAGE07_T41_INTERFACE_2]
11 PAGE11_SD_AUDIO: size A3
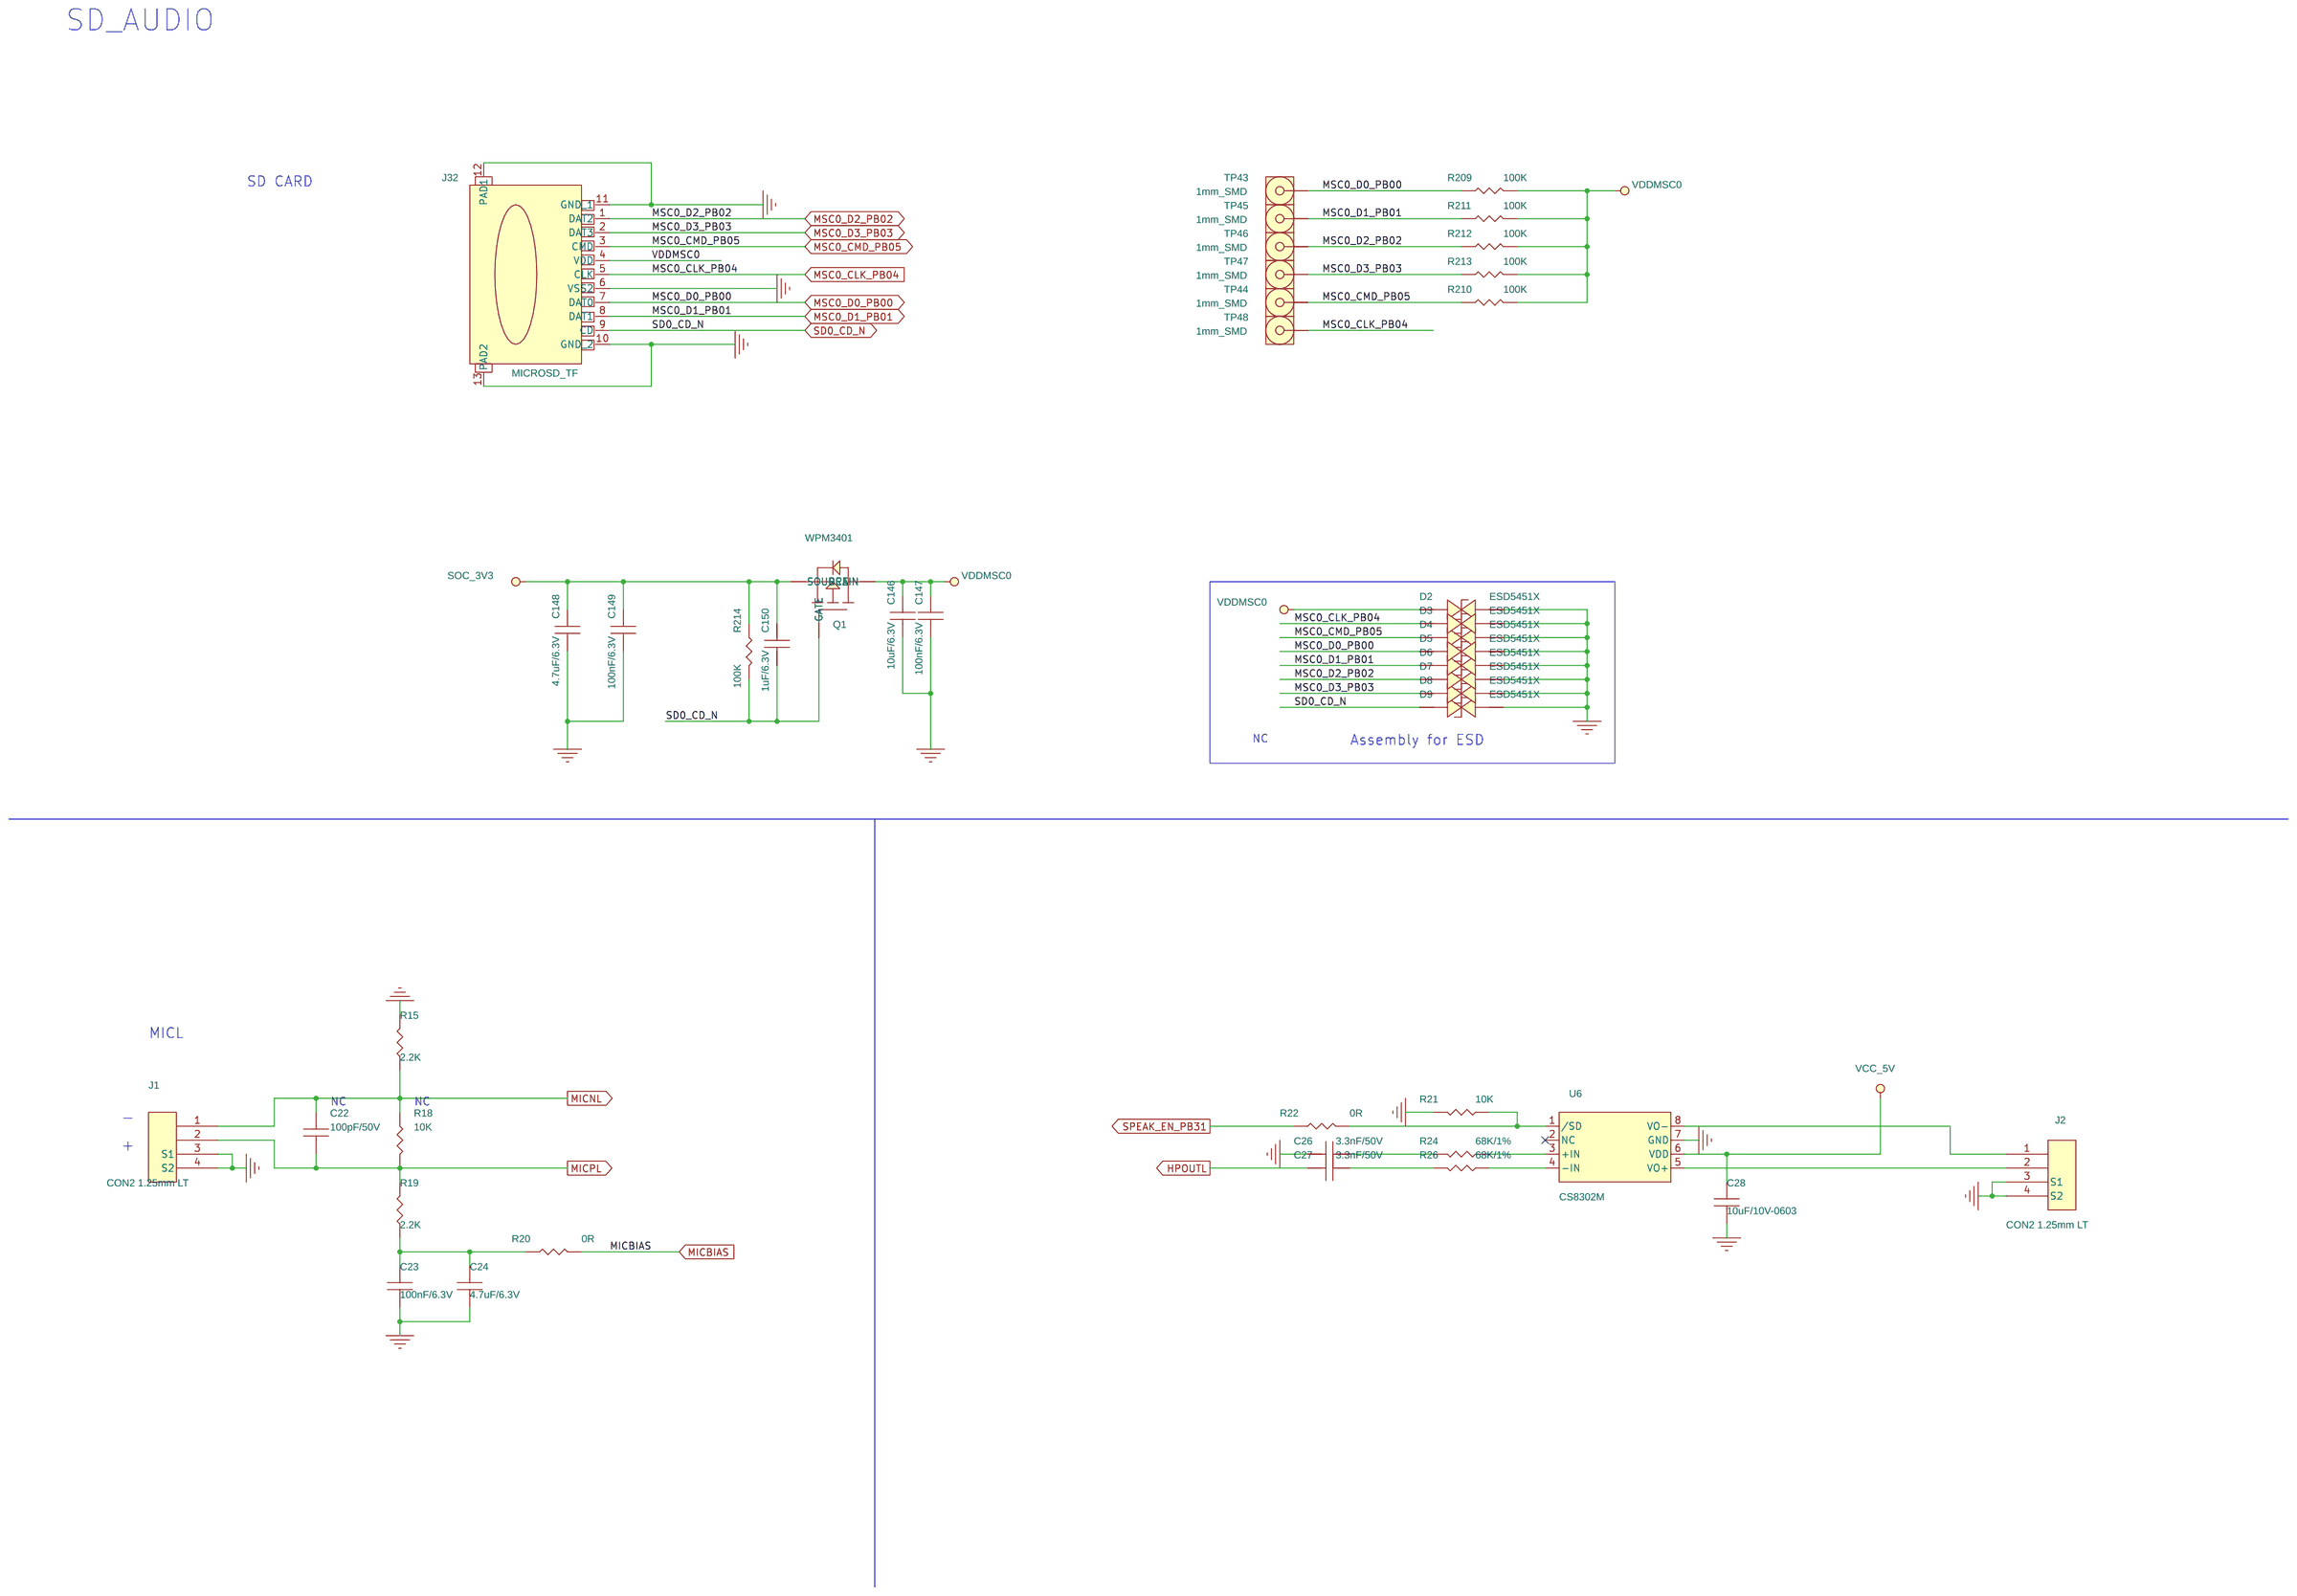
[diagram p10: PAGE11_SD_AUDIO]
12 PAGE09_ETH_PHY: size A3
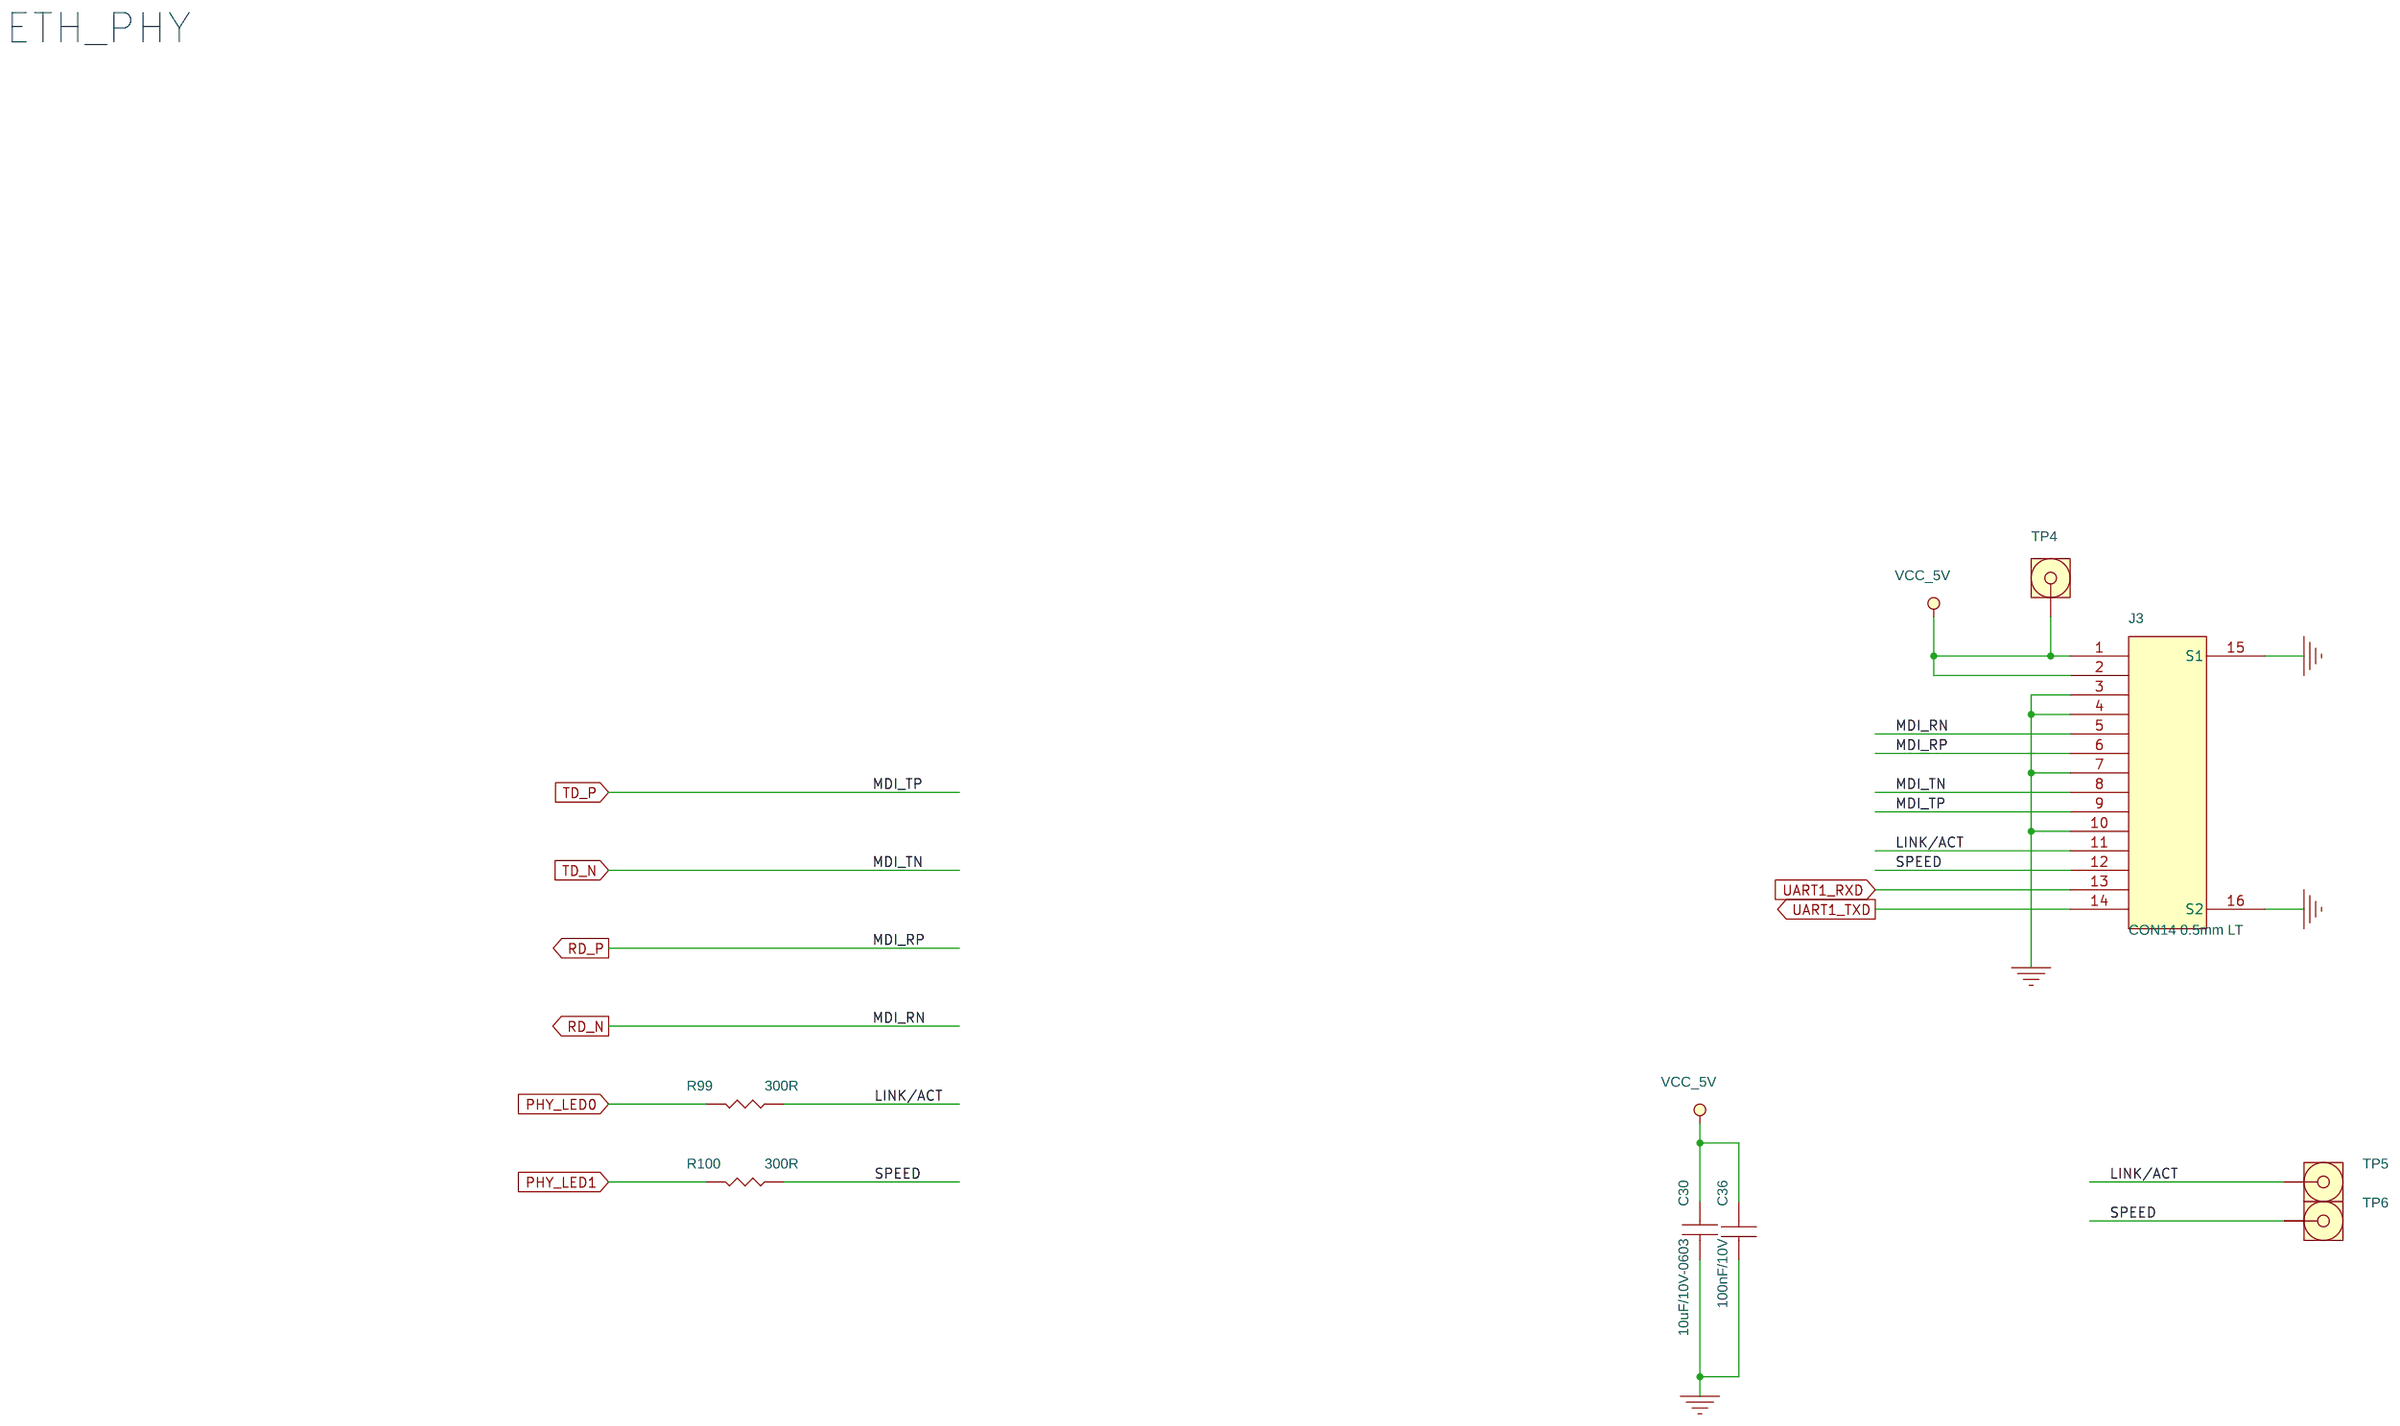
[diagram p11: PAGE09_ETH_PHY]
13 PAGE13_REVISION-HISTORY
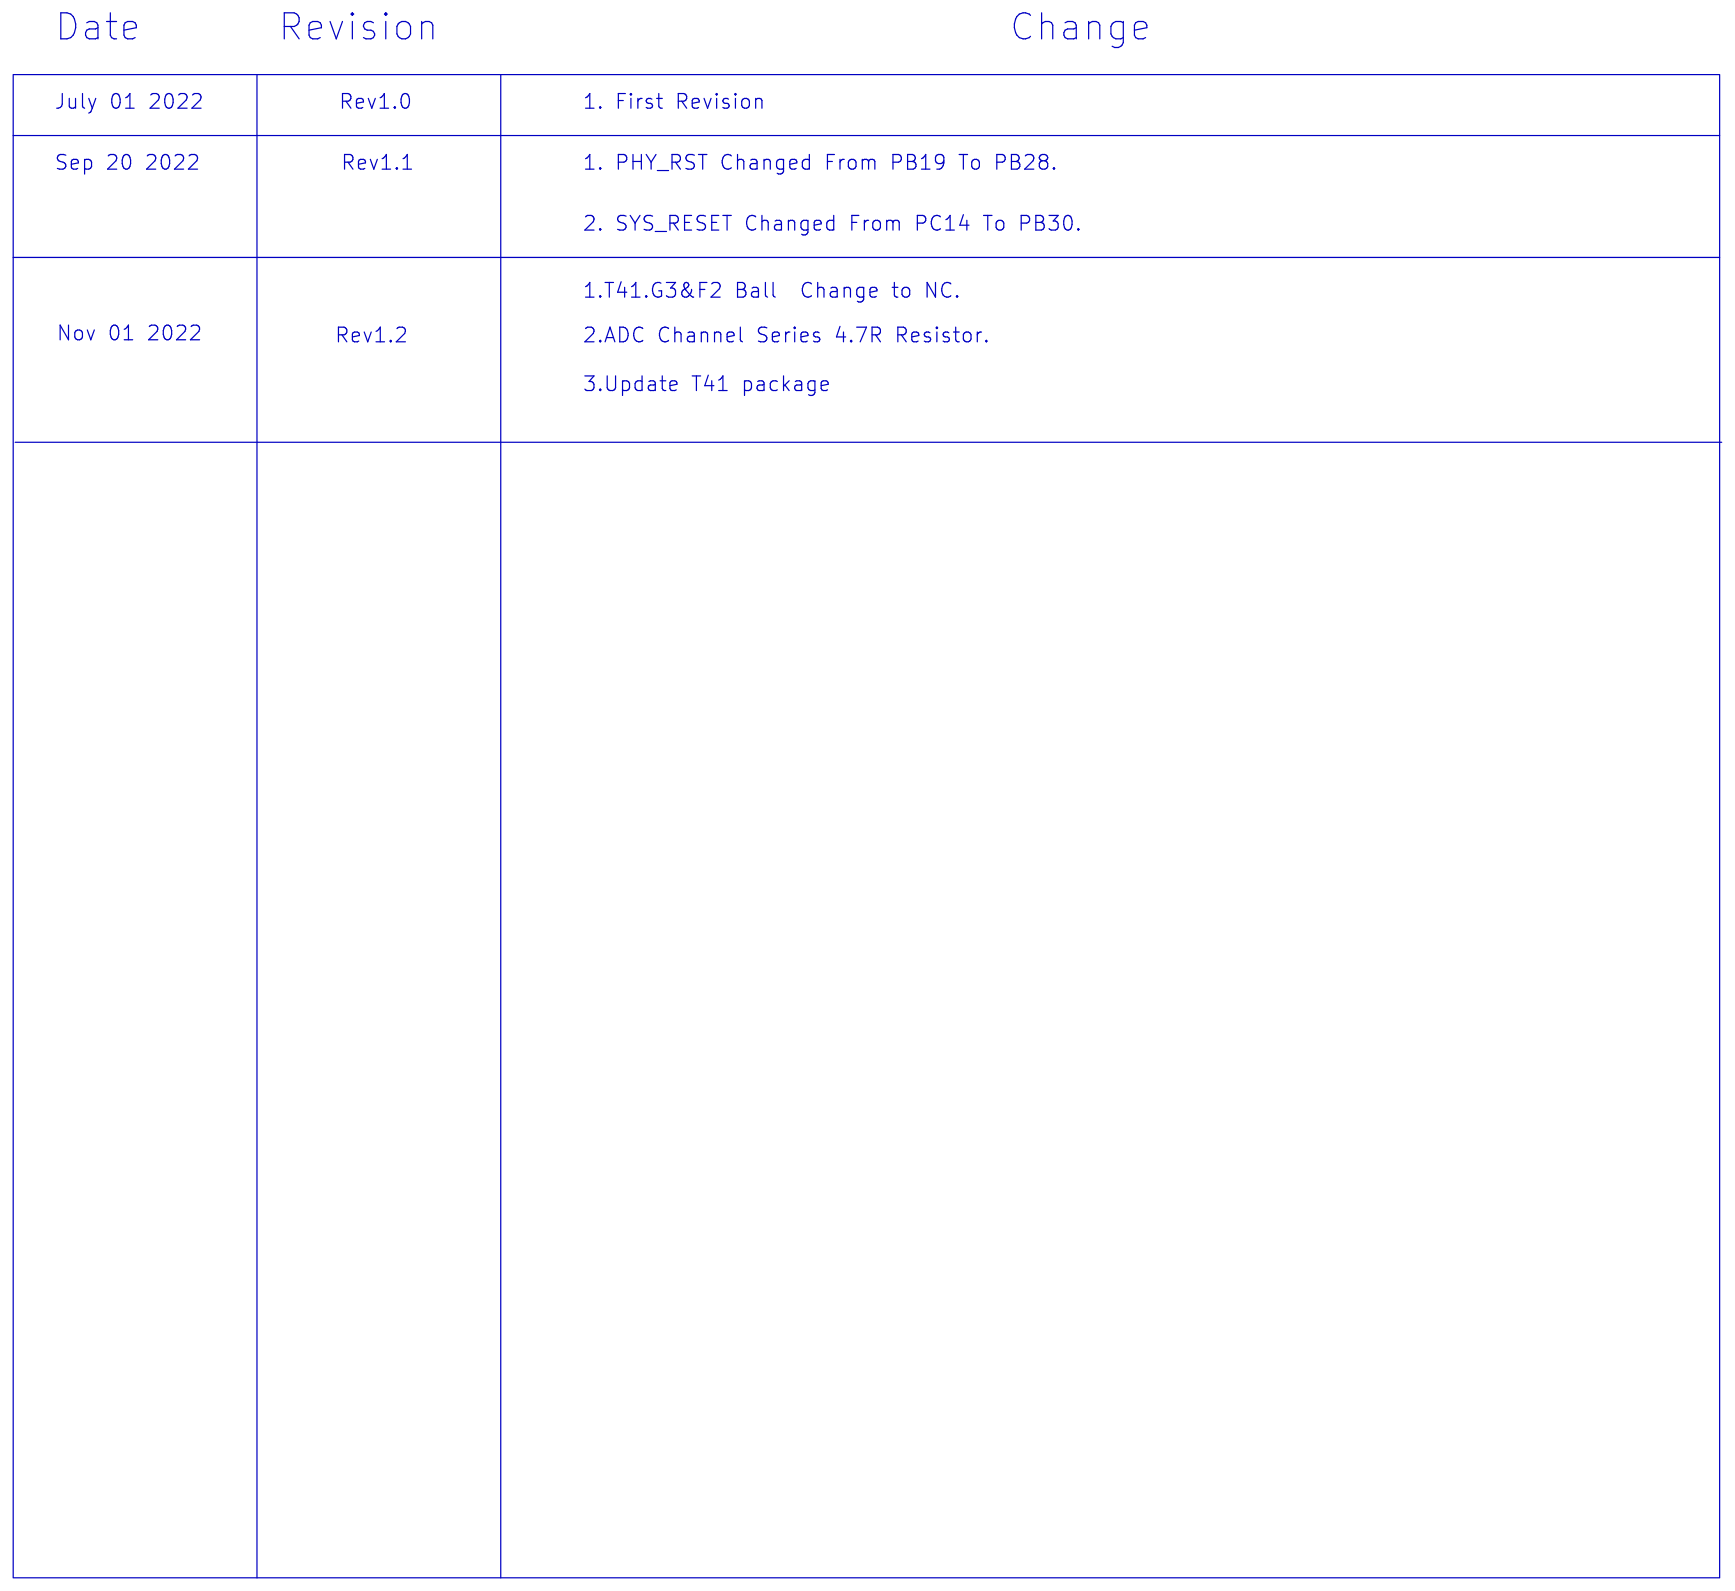
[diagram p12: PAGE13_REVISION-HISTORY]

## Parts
sheet PAGE03_POWER-SUPPLY
C1  10uF/10V-0603  [C0603]
C2  10uF/6.3V  [C0402_E]
C3  100nF/10V  [C0402]
C4  100nF/6.3V  [C0402]
C5  22pF/50V  [C0402]
C6  22pF/50V  [C0402]
C7  10uF/6.3V  [C0402_E]
C8  10uF/10V-0603  [C0603]
C9  100nF/10V  [C0402]
C10  100nF/10V  [C0402]
C11  22pF/50V  [C0402]
C12  10uF/6.3V  [C0402_E]
C13  10uF/10V-0603  [C0603]
C14  100nF/10V  [C0402]
C15  22pF/50V  [C0402]
C16  10uF/6.3V  [C0402_E]
C18  10uF/10V-0603  [C0603]
C20  100nF/10V  [C0402]
HOLE1  T POINT R  [H3D5MM_2D2MM]
HOLE2  T POINT R  [H3D5MM_2D2MM]
HOLE3  T POINT R  [H3D5MM_2D2MM]
HOLE4  T POINT R  [H3D5MM_2D2MM]
L1  1uH/2.7A  [L2016]
L2  2.2uH/1.3A-2016  [L2016]
L3  2.2uH/1.3A-2016  [L2016]
L4  2.2uH/1.3A-2016  [L2016]
R1  100K  [R0402]
R2  100K  [R0402]
R3  150K/1%  [R0402]
R4  33.2K/1%  [R0402]
R5  100K/1%  [R0402]
R6  300K/1%  [R0402]
R7  100K  [R0402]
R8  200K/1%  [R0402]
R9  100K/1%  [R0402]
R10  100K  [R0402]
R11  150K/1%  [R0402]
R13  120K/1%  [R0402]
TP1  1mm_SMD  [TEST_SMD]
TP2  1mm_SMD  [TEST_SMD]
TP3  1mm_SMD  [TEST_SMD]
TP25  1mm_SMD  [TEST_SMD]
U1  LN5058  [SOT23-5]
U2  ETA3409  [SOT23-5]
U3  LN5058  [SOT23-5]
U5  LN5058  [SOT23-5]
sheet PAGE04_T41_POWER
C48  10uF/6.3V  [C0402_E]
C203  10uF/6.3V  [C0402_E]
C206  10uF/6.3V  [C0402_E]
C212  100nF/6.3V  [C0402]
C213  10uF/6.3V  [C0402_E]
C214  100nF/6.3V  [C0402]
C215  100nF/6.3V  [C0402]
C216  100nF/6.3V  [C0402]
C217  10nF/6.3V  [C0402]
C218  10nF/6.3V  [C0402]
C231  100nF/6.3V  [C0402]
C232  100nF/6.3V  [C0402]
C233  10uF/6.3V  [C0402_E]
C234  10uF/6.3V  [C0402_E]
C238  10uF/6.3V  [C0402_E]
C239  100nF/6.3V  [C0402]
C240  10nF/6.3V  [C0402]
C241  10nF/6.3V  [C0402]
C244  100nF/6.3V  [C0402]
C250  100nF/6.3V  [C0402]
R75  240R/1%  [R0402]
R345  240R/1%  [R0402]
R346  10K/1%  [R0402]
R347  10K/1%  [R0402]
U4  T41 BGA232  [BGA232_0D65_T41]  (sections A,B,C,D)
sheet PAGE05_T41_SYS_APeripheral
C17  100nF/6.3V  [C0402]
C21  12pF/50V  [C0402]
C25  12pF/50V  [C0402]
C34  100nF/6.3V  [C0402]
C53  100nF/6.3V  [C0402]
C54  10uF/6.3V  [C0402_E]
C61  100nF/6.3V  [C0402]
C63  100nF/6.3V  [C0402]
C65  100nF/6.3V  [C0402]
C66  4.7uF/6.3V  [C0402]
C67  100nF/6.3V  [C0402]
C68  4.7uF/6.3V  [C0402]
C69  100nF/6.3V  [C0402]
C70  100nF/6.3V  [C0402]
C71  100nF/6.3V  [C0402]
C90  100nF/6.3V  [C0402]
C140  100nF/6.3V  [C0402]
C143  1uF/6.3V  [C0402]
C248  100nF/6.3V  [C0402]
C255  100nF/6.3V  [C0402]
FB1  1000ohm/250mA  [FB0402]
FB7  1000ohm/250mA  [FB0402]
R12  10K  [R0402]
R14  33R  [R0402]
R17  1M  [R0402]
R25  4.7R/5%  [R0402]
R59  100K  [R0402]
R60  100K  [R0402]
R61  100K  [R0402]
R343  1K  [R0402]
U13  GD5F1GQ5UEYIGR  [WSON8_1D27_8X6]
Y1  24M 2016  [CRY_2D5X2D0]
sheet PAGE06_T41_INTERFACE_1
C74  100nF/6.3V  [C0402]
C76  1uF/6.3V  [C0402]
C79  100nF/6.3V  [C0402]
C86  100nF/6.3V  [C0402]
C88  100nF/6.3V  [C0402]
C175  1uF/6.3V  [C0402]
C176  100nF/6.3V  [C0402]
C187  100nF/6.3V  [C0402]
R16  10K  [R0402]
R23  10K  [R0402]
R50  1K  [R0402]
R51  10K  [R0402]
R52  10K  [R0402]
R57  33R  [R0402]
R207  33R  [R0402]
R312  2.49K/1%  [R0402]
R313  10K  [R0402]
R314  10K  [R0402]
R315  1K  [R0402]
sheet PAGE07_T41_INTERFACE_2
C96  100nF/6.3V  [C0402]
C144  100nF/6.3V  [C0402]
C189  100nF/6.3V  [C0402]
sheet PAGE08_USB_WIFI
C83  10pF/50V  [C0402]
C84  10uF/6.3V  [C0402_E]
C89  100nF/6.3V  [C0402]
C91  1uF/6.3V  [C0402]
C97  5.6pF/50V  [C0402]
J9  IPEX  [ANT3_U_FL_R_SMD]
L5  INDUCTOR  [L0402]
Q2  WPM3401  [SOT23]
Q3  SST3904  [SOT23]
R68  0R-0603  [R0603]
R69  100K  [R0402]
R70  1K  [R0402]
R71  10K  [R0402]
U14  BL-M8188FU3-B  [LCC6_BLM8188FU3]
sheet PAGE09_ETH_PHY
C30  10uF/10V-0603  [C0603]
C36  100nF/10V  [C0402]
J3  CON14 0.5mm LT  [FPC-CON14-0D5-LT]
R99  300R  [R0402]
R100  300R  [R0402]
TP4  1mm_SMD  [TEST_SMD]
TP5  1mm_SMD  [TEST_SMD]
TP6  1mm_SMD  [TEST_SMD]
sheet PAGE10_SENSOR
C31  1uF/6.3V  [C0402]
C32  2.2uF/10V  [C0402]
C33  2.2uF/10V  [C0402]
C35  100nF/6.3V  [C0402]
C37  1uF/6.3V  [C0402]
C38  100nF/6.3V  [C0402]
C39  100nF/6.3V  [C0402]
C40  10uF/6.3V  [C0402_E]
C41  10uF/6.3V  [C0402_E]
C42  100nF/6.3V  [C0402]
C43  10uF/6.3V  [C0402_E]
C44  100nF/6.3V  [C0402]
C45  10uF/6.3V  [C0402_E]
C46  100nF/6.3V  [C0402]
C47  1uF/6.3V  [C0402]
C49  1uF/6.3V  [C0402]
C50  100nF/6.3V  [C0402]
C52  10nF/6.3V  [C0402]
C75  1uF/6.3V  [C0402]
J4  CON2 1.25mm LT  [CON2-1D25-LT]
J5  Sensor  [IRCUT-32X28-16_8x14_9]
R27  0R  [R0402]
R28  10K  [R0402]
R29  10K  [R0402]
R30  4.7K  [R0402]
R32  4.7K  [R0402]
R33  10K  [R0402]
R34  10K  [R0402]
R35  10K  [R0402]
R36  4.7K  [R0402]
R37  0R  [R0402]
R38  150K  [R0402]
R39  0R-0603  [R0603]
R40  100K  [R0402]
TP24  1mm_SMD  [TEST_SMD]
U7  GC4663  [BGA41_0D73X0D65_GC4663]
U9  BA6208  [SOP8_1D27]
U10  SGM2019-2.8YN5G  [SOT23-5]
U11  S-1339D13  [SOT23-5]
sheet PAGE11_SD_AUDIO
C22  100pF/50V  [C0402]
C23  100nF/6.3V  [C0402]
C24  4.7uF/6.3V  [C0402]
C26  3.3nF/50V  [C0402]
C27  3.3nF/50V  [C0402]
C28  10uF/10V-0603  [C0603]
C146  10uF/6.3V  [C0402_E]
C147  100nF/6.3V  [C0402]
C148  4.7uF/6.3V  [C0402]
C149  100nF/6.3V  [C0402]
C150  1uF/6.3V  [C0402]
D2  ESD5451X  [ESD0402]
D3  ESD5451X  [ESD0402]
D4  ESD5451X  [ESD0402]
D5  ESD5451X  [ESD0402]
D6  ESD5451X  [ESD0402]
D7  ESD5451X  [ESD0402]
D8  ESD5451X  [ESD0402]
D9  ESD5451X  [ESD0402]
J1  CON2 1.25mm LT  [CON2-1D25-LT]
J2  CON2 1.25mm LT  [CON2-1D25-LT]
J32  MICROSD_TF  [TFCARD]
Q1  WPM3401  [SOT23]
R15  2.2K  [R0402]
R18  10K  [R0402]
R19  2.2K  [R0402]
R20  0R  [R0402]
R21  10K  [R0402]
R22  0R  [R0402]
R24  68K/1%  [R0402]
R26  68K/1%  [R0402]
R209  100K  [R0402]
R210  100K  [R0402]
R211  100K  [R0402]
R212  100K  [R0402]
R213  100K  [R0402]
R214  100K  [R0402]
TP43  1mm_SMD  [TEST_SMD]
TP44  1mm_SMD  [TEST_SMD]
TP45  1mm_SMD  [TEST_SMD]
TP46  1mm_SMD  [TEST_SMD]
TP47  1mm_SMD  [TEST_SMD]
TP48  1mm_SMD  [TEST_SMD]
U6  CS8302M  [MSOP8_0D65]
sheet PAGE12_MOTOR_RST_LED
C29  10uF/10V-0603  [C0603]
C51  10uF/10V-0603  [C0603]
C58  100nF/10V  [C0402]
C72  100nF/6.3V  [C0402]
C73  100nF/10V  [C0402]
C77  10uF/10V-0603  [C0603]
D1  ESD5451X  [ESD0402]
J6  CON5 1.5mm LT  [CON5-1D5-LT]
J7  CON5 1.5mm LT  [CON5-1D5-LT]
J8  CON8 1.27mm Female  [HEADER4X2FM_1D27_SMD]
R42  100K  [R0402]
R43  100K  [R0402]
R44  100K  [R0402]
R45  100K  [R0402]
R46  100K  [R0402]
R47  100K  [R0402]
R48  100K  [R0402]
R49  100K  [R0402]
R53  10K  [R0402]
R54  0R  [R0402]
R55  1K  [R0402]
R56  0R  [R0402]
R58  33.2K/1%  [R0402]
SW2  ST1112A  [SW2_SMD_ST1112A]
TP9  1mm_SMD  [TEST_SMD]
TP10  1mm_SMD  [TEST_SMD]
TP11  1mm_SMD  [TEST_SMD]
TP12  1mm_SMD  [TEST_SMD]
TP13  1mm_SMD  [TEST_SMD]
TP14  1mm_SMD  [TEST_SMD]
TP15  1mm_SMD  [TEST_SMD]
TP16  1mm_SMD  [TEST_SMD]
TP17  1mm_SMD  [TEST_SMD]
TP18  1mm_SMD  [TEST_SMD]
TP19  1mm_SMD  [TEST_SMD]
TP20  1mm_SMD  [TEST_SMD]
TP21  1mm_SMD  [TEST_SMD]
U12  ULN2803A  [QFN20L_0D5_ULN2803]

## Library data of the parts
C1 C8 C13 C18 = CAP: Capacitor-10uF,+/-20%,X5R,10V-0603; Part Number: 02.0026.00; Part Type: 0603表贴普通电容; 供应商: YAGEO / Murata; 供应商2: Murata; 规格型号1: CC0603MRX5R6BB106 / GRM188R61A106KE47D; 联系人: 谢苏云; 联系人2: 吴铭; 手机: 15900554174; 手机2: 13761466262; 邮箱: susan.xie@murata.com; 邮箱2: cherry.wu@murata.com
C2 C7 C12 C16 = CAP: Capacitor-10uF,+/-20%,X5R,6.3V-0402+; Part Number: 02.0034.00; Part Type: 0402表贴普通电容; 供应商: YAGEO / Murata; 供应商2: Murata; 规格型号1: CC0402MRX5R5BB106 / GRM155R60J106ME44D; 联系人: 谢苏云; 联系人2: 吴铭; 手机: 15900554174; 手机2: 13761466262; 邮箱: susan.xie@murata.com; 邮箱2: cherry.wu@murata.com
C3 C9 C14 C20 C36 = CAP: Capacitor-100nF,+/-10%,X7R,10V-0402; Part Number: 02.0075.00; Part Type: 0402表贴普通电容; 供应商: Murata; 供应商1: Eyang; 规格型号1: GRM155R71A104KA01D; 联系人: 谢苏云; 联系人1: 何俊; 手机: 15900554174; 手机1: 18317187178; 邮箱: susan.xie@murata.com; 邮箱1: hejunxs@szeyang.com
C4 C89 = CAP: Capacitor-100nF,+/-10%,X7R,6.3V-0402; Part Number: 02.0075.00; Part Type: 0402表贴普通电容; 供应商: Murata; 供应商1: Eyang; 规格型号1: GRM155R70J104KA01D; 联系人: 谢苏云; 联系人1: 何俊; 手机: 15900554174; 手机1: 18317187178; 邮箱: susan.xie@murata.com; 邮箱1: hejunxs@szeyang.com
C5 C11 C15 = CAP: Capacitor-22pF,+/-5%,C0G,50V-0402; Part Number: 02.0008.00; Part Type: 0402表贴普通电容; 供应商: YAGEO / Murata; 供应商2: Murata; 规格型号1: CC0402JRNPO9BN220 / GRM1552C1H220JA01D; 联系人: 谢苏云; 联系人2: 吴铭; 手机: 15900554174; 手机2: 13761466262; 邮箱: susan.xie@murata.com; 邮箱2: cherry.wu@murata.com
C6 = CAP: Capacitor-22pF,+/-5%,C0G,50V-0402; Part Number: 02.0008.00; Part Type: 0402表贴普通电容; 供应商: YAGEO / Murata; 规格型号1: CC0402JRNPO9BN220 / GRM1552C1H220JA01D; 联系人: 谢苏云; 手机: 15900554174; 邮箱: susan.xie@murata.com
C10 C58 C73 = CAP: Capacitor-100nF,+/-10%,X7R,10V-0402; Part Number: 02.0075.00; Part Type: 0402表贴普通电容; 供应商: Murata; 规格型号1: GRM155R71A104KA01D; 联系人: 谢苏云; 手机: 15900554174; 邮箱: susan.xie@murata.com
HOLE1-HOLE4 = T_POINT_R
L1 = INDUCTOR: Murata DFE201612P-1R0M=P2 1uH/2.7A（Tr=40）±20% H=1.2mm POWER INDUCTOR; Part Number: 03.0035.00; Part Type: 2016表贴电感; 供应商: Murata; 规格型号1: DFE201612P-1R0M=P2; 联系人: 谢苏云; 手机: 15900554174; 邮箱: susan.xie@murata.com; Datasheet: DFE201612P_Murata data sheet_170130.pdf
L2-L4 = INDUCTOR: MuRata 1285/6AS-H-2R2MS=P2 2.2uH/1.3A-2016 POWER INDUCTOR; Part Number: 03.0005.00; Part Type: 2016表贴电感; 供应商: Murata; 规格型号1: 1286AS-H-2R2MS=P2; 联系人: 谢苏云; 手机: 15900554174; 邮箱: susan.xie@murata.com; Datasheet: DFE201612C_Murata data sheet150423.pdf
R1 R2 R7 R10 R40 R42-R49 R59-R61 R69 R209-R214 = RES: Resistor-100K,+/-5%,1/16W-0402; Part Number: 01.0041.00; Part Type: 0402表贴普通电阻; 供应商: 厚声; 规格型号1: 0402WGJ0104TCE
R3 R11 = RES: Resistor-150K,+/-1%,1/16W-0402; Part Number: 01.0043.00; Part Type: 0402表贴高精度电阻; 供应商: 厚声; 规格型号1: 0402WGF1503TCE
R4 R58 = RES: Resistor-33.2K,+/-1%,1/16W-0402; Part Number: 01.0032.00; Part Type: 0402表贴高精度电阻; 供应商: 厚声; 规格型号1: 0402WGF3322TCE
R5 R9 = RES: Resistor-100K,+/-1%,1/16W-0402; Part Number: 01.0040.00; Part Type: 0402表贴高精度电阻; 供应商: 厚声; 规格型号1: 0402WGF1003TCE
R6 = RES: Resistor-300K,+/-1%,1/16W-0402; Part Number: 01.0046.00; Part Type: 0402表贴高精度电阻; 供应商: 厚声; 规格型号1: 0402WGF3003TCE
R8 = RES: Resistor-200K,+/-1%,1/16W-0402; Part Number: 01.0045.00; Part Type: 0402表贴高精度电阻; 供应商: 厚声; 规格型号1: 0402WGF2003TCE
R13 = RES: Resistor-120K,+/-1%,1/16W-0402; Part Number: 01.0042.00; Part Type: 0402表贴高精度电阻; 供应商: 厚声; 规格型号1: 0402WGF1203TCE
TP1-TP6 TP9-TP21 TP24 TP25 TP43-TP48 = TP: SMD Test Point φ1mm; Part Number: AA.0001.00; Part Type: Test Point
U1 U3 U5 = SY8088: 南麟 LN5058 1.5A 1.5MHz Input-2.5V~6.2V Buck Regulator; Part Number: 05.2024.00; Part Type: 降压型DCDC; 供应商: 芯晶图; 联系人: 费军; 手机: 13808850029; 邮箱: 2853085379@qq.com; Datasheet: LN5058_C.pdf
U2 = SY8088: ETA ETA3409 2A 3MHz Input-2.6V~5.5V Buck Regulator; Part Number: 05.2016.00; Part Type: 降压型DCDC; 供应商: ETA; 联系人: 徐卓荣; 手机: 13923780263; 邮箱: xuzhuorong@etasolution.com; Datasheet: ETA3409_V1.2.pdf
C40 C41 C43 C45 C48 C54 C84 C146 C203 C206 C213 C233 C234 C238 = CAP: Capacitor-10uF,+/-20%,X5R,6.3V-0402+; Part Number: 02.0034.00; Part Type: 0402表贴普通电容; 供应商: YAGEO / Murata; 规格型号1: CC0402MRX5R5BB106 / GRM155R60J106ME44D; 联系人: 谢苏云; 手机: 15900554174; 邮箱: susan.xie@murata.com
C17 C23 C34 C35 C38 C39 C42 C44 C46 C50 C53 C61 C63 C65 C67 C69-C72 C74 C79 C86 C88 C90 C96 C140 C144 C147 C149 C176 C187 C189 C212 C214-C216 C231 C232 C239 C244 C248 C250 C255 = CAP: Capacitor-100nF,+/-10%,X7R,6.3V-0402; Part Number: 02.0075.00; Part Type: 0402表贴普通电容; 供应商: Murata; 规格型号1: GRM155R70J104KA01D; 联系人: 谢苏云; 手机: 15900554174; 邮箱: susan.xie@murata.com
C52 C217 C218 C240 C241 = CAP: Capacitor-10nF,+/-10%,X7R,6.3V-0402; Part Number: 02.0075.00; Part Type: 0402表贴普通电容; 供应商: Murata; 规格型号1: GRM155R70J102KA01D; 联系人: 谢苏云; 手机: 15900554174; 邮箱: susan.xie@murata.com
R75 R345 = RES: Resistor-240R,+/-1%,1/16W-0402; Part Number: 01.0010.00; Part Type: 0402表贴高精度电阻; 供应商: 厚声; 规格型号1: 0402WGF2400TCE
R346 R347 = RES: Resistor-10K,+/-1%,1/16W-0402; Part Number: 01.0024.00; Part Type: 0402表贴高精度电阻; 供应商: 厚声; 规格型号1: 0402WGF1002TCE
U4 = T41_BGA232: Ingenic T41 Smart Video Processor FBGA 232Ball 0.65mmPitch 11mmX11mm; Part Number: 06.0137.00; Part Type: CPU; 供应商: Ingenic; 规格型号1: T41
C21 C25 = CAP: Capacitor-12pF,+/-5%,C0G,50V-0402; ID: 8; Part Number: 02.0006.00; Part Type: 0402表贴普通电容; 供应商: YAGEO / Murata; 供应商2: Murata; 规格型号1: CC0402JRNPO9BN120 / GCM1555C1H120JA16D; 联系人: 谢苏云; 联系人2: 吴铭; 手机: 15900554174; 手机2: 13761466262; 邮箱: susan.xie@murata.com; 邮箱2: cherry.wu@murata.com
C24 C66 C68 C148 = CAP: Capacitor-4.7uF,+/-20%,X5R,6.3V-0402; Part Number: 02.0018.00; Part Type: 0402表贴普通电容; 供应商: YAGEO / Murata; 规格型号1: CC0402MRX5R5BB475 / GRM153R60J475ME15D; 联系人: 谢苏云; 手机: 15900554174; 邮箱: susan.xie@murata.com
C31 C37 C47 C49 C75 C76 C91 C143 C150 C175 = CAP: Capacitor-1uF,+/-10%,X7R,6.3V-0402; Part Number: 02.0076.00; Part Type: 0402表贴普通电容; 供应商: Murata; 规格型号1: GRM155R70J105KA12; 联系人: 谢苏云; 手机: 15900554174; 邮箱: susan.xie@murata.com
FB1 FB7 = BEAD: Murata BLM15HG102SN1D Z=1000ohm@100MHz 250mA 1.1ohm 25%; Part Number: 03.1001.00; Part Type: 0402表贴磁珠; 供应商: Murata; 规格型号1: BLM15HG102SN1D; 联系人: 谢苏云; 手机: 15900554174; 邮箱: susan.xie@murata.com; Datasheet: BLM15HG.pdf
R12 R16 R18 R21 R23 R33-R35 R51-R53 R71 R313 R314 = RES: Resistor-10K,+/-5%,1/16W-0402; Part Number: 01.0023.00; Part Type: 0402表贴普通电阻; 供应商: 厚声; 规格型号1: 0402WGJ0103TCE
R14 R57 R207 = RES: Resistor-33R,+/-5%,1/16W-0402; Part Number: 01.0005.00; Part Type: 0402表贴普通电阻; 供应商: 厚声; 规格型号1: 0402WGJ0330TCE
R17 = RES: Resistor-1M,+/-5%,1/16W-0402; ID: 49; Part Number: 01.0049.00; Part Type: 0402表贴普通电阻; 供应商: 厚声; 供应商1: Eyang; 规格型号1: 0402WGJ0105TCE; 联系人1: 何俊; 手机1: 18317187178; 邮箱1: hejunxs@szeyang.com
R25 = RES: Resistor-4.7R,+/-5%,1/16W-0402; Part Number: 01.0126.00; Part Type: 0402表贴普通电阻; 供应商: 厚声; 规格型号1: 0402WGJ470TCE
R50 R55 R70 R315 R343 = RES: Resistor-1K,+/-5%,1/16W-0402; Part Number: 01.0014.00; Part Type: 0402表贴普通电阻; 供应商: 厚声; 规格型号1: 0402WGJ0102TCE
U13 = SPI_NAND: Giga Device GD5F1GQ5UEYIGR 1Gbit 3.3V SPI NAND FLASH MEMORY; Part Number: 06.0110.01; Part Type: SPI NAND; 供应商: Giga Device; 联系人: 薛霆; 手机: 13910816516; 邮箱: ting.xue@gigadevice.com; Datasheet: GD5F1GQ5xExxG_v1.1.pdf
Y1 = XTAL_P4: Murata XRCGB24M000F2P01R0 Crystal initial ±20ppm 8pF; Part Number: 08.0001.00; Part Type: Crystal; 供应商: Murata; 规格型号1: XRCGB24M000F2P01R0; 联系人: 谢苏云; 手机: 15900554174; 邮箱: susan.xie@murata.com; Datasheet: XRCGB24M000F2P01R0.pdf
R312 = RES: Resistor-2.49K,+/-1%,1/16W-0402; Part Number: 01.0134.00; Part Type: 0402表贴高精度电阻; 供应商: 厚声; 规格型号1: 0402WGF2491TCE
C83 = CAP: Capacitor-10pF,+/-5%,C0G,50V-0402; Part Number: 02.0035.00; Part Type: 0402表贴普通电容; 供应商: YAGEO / Murata; 规格型号1: CC0402JRNPO9BN100 / GJM1555C1H100JB01D; 联系人: 谢苏云; 手机: 15900554174; 邮箱: susan.xie@murata.com
C97 = CAP: Capacitor-5.6pF,+/-0.1pF,C0G,50V-0402; Part Number: 02.0040.00; Part Type: 0402表贴普通电容; 供应商: YAGEO / Murata; 规格型号1: CC0402BRNPO9BN5R6 / GCM1555C1H5R6BA16D; 联系人: 谢苏云; 手机: 15900554174; 邮箱: susan.xie@murata.com
J9 = IPEX: IPEX WIFI ANT; Part Number: 10.0014.00; Part Type: ANT; 规格型号1: Ipex U.FL-R-SMT天线座; Datasheet: IPEX-端子封装.pdf
L5 = INDUCTOR: TAIYO HK10052N7S-T 2.7nH/0.3A-0402 POWER INDUCTOR; Part Number: 03.0001.00; Part Type: 0402射频电感; 供应商: TAIYO; 规格型号1: HK10052N7S-T; 联系人: 陈曦; 手机: 15827156663; 邮箱: coen@csty.yuden.co.jp; Datasheet: HK10052N7S-T_SS.pdf
Q1 Q2 = P_MOS: WILL WPM3401 P-Channel MOSFET; Part Number: 09.0008.00; Part Type: MOS管; 供应商: Will; 联系人: 安志鹏; 手机: 18321800431; 邮箱: an.zhipeng@sh-willsemi.com; Datasheet: WPM340_datasheet.pdf
Q3 = NPN: ROHM SST3904 NPN General Purpose Transistor; Part Number: 09.0017.00; Part Type: 三极管; 供应商: ROHM; 规格型号1: SST3904T116; 联系人: 贾文; 手机: 13817895109; 邮箱: jossie-jia@rohm.com.cn; Datasheet: sst3904-e.pdf
R39 R68 = RES: Resistor-0R,+/-5%,1/10W-0603; Part Number: 01.0051.00; Part Type: 0603表贴普通电阻; 供应商: 厚声; 规格型号1: 0603WAJ0000T5E
U14 = USBWIFI_T: LB-LINK BL-M8188FU3-B IEEE 802.11b/g/n (1T1R) USB WLAN Module; Part Number: 10.0038.00; Part Type: WIFI Module; 供应商: LB-LINK; 联系人: 夏建军; 手机: 13798358430; 邮箱: xia@b-link.net.cn; Datasheet: BL-M8188FU3-B 游标孔出信号.pdf
C28-C30 C51 C77 = CAP: Capacitor-10uF,+/-20%,X5R,10V-0603; Part Number: 02.0026.00; Part Type: 0603表贴普通电容; 供应商: YAGEO / Murata; 规格型号1: CC0603MRX5R6BB106 / GRM188R61A106KE47D; 联系人: 谢苏云; 手机: 15900554174; 邮箱: susan.xie@murata.com
J3 = FPCCON_7X2: HOLY 0.5mm pitch FPC LT 14 Pin Connector; Part Number: 04.0084.00; Part Type: 0.5mm立贴FPC连接器; 供应商: 深圳宏利电子; 规格型号1: FPC0.5mm-14P立贴正位; 联系人: 谢素平; 手机: 16717558767; Datasheet: 0.5mm立式正位全包.pdf
R99 R100 = RES: Resistor-300R,+/-5%,1/16W-0402; Part Number: 01.0011.00; Part Type: 0402表贴普通电阻; 供应商: 厚声; 规格型号1: 0402WGJ0301TCE
C32 C33 = CAP: Capacitor-2.2uF,+/-10%,X5R,10V-0402; Part Number: 02.0017.00; Part Type: 0402表贴普通电容; 供应商: YAGEO / Murata; 规格型号1: CC0402KRX5R6BB225 / GRM155R61A225KE95D; 联系人: 谢苏云; 手机: 15900554174; 邮箱: susan.xie@murata.com
J1 J2 J4 = CON_2X1: HOLY 1.25mm Pitch 2P LT SMD Connector; Part Number: 04.0001.00; Part Type: 1.25mm立贴连接器; 供应商: 深圳宏利电子; 规格型号1: 1.25mm立贴2P插座; 联系人: 谢素平; 手机: 16717558767; Datasheet: 1.25mm 立贴.pdf
J5 = Sensor
R20 R22 R27 R37 R54 R56 = RES: Resistor-0R,+/-5%,1/16W-0402; Part Number: 01.0001.00; Part Type: 0402表贴普通电阻; 供应商: 厚声; 规格型号1: 0402WGJ0000TCE
R28 R29 = RES: Resistor-10K,+/-5%,1/16W-0402; Part Number: 01.0023.00; Part Type: 0402表贴普通电阻; 供应商: 厚声; 供应商1: Eyang; 规格型号1: 0402WGJ0103TCE; 联系人1: 何俊; 手机1: 18317187178; 邮箱1: hejunxs@szeyang.com
R30 R32 R36 = RES: Resistor-4.7K,+/-5%,1/16W-0402; Part Number: 01.0019.00; Part Type: 0402表贴普通电阻; 供应商: 厚声; 规格型号1: 0402WGJ0472TCE
R38 = RES: Resistor-150K,+/-5%,1/16W-0402; Part Number: 01.0026.00; Part Type: 0402表贴普通电阻; 供应商: 厚声; 规格型号1: 0402WGJ0154TCE
U7 = GC4663: GalaxyCore GC4663 1/3" 400W@30fps CMOS Image Sensor; Part Number: 07.0074.00; Part Type: GC Sensor; 供应商: 格科微; 联系人: 杨利春; 手机: 18576613918; 邮箱: simon_yang@gcoreinc.com; Datasheet: AE-4M-3018 GC4663 CSP Datasheet V1.2 20210511.pdf
U9 = BA6208: UTC BA6208 REVERSIBLE MOTOR DRIVER For IR-Cut; Part Number: 06.0033.00; Part Type: 驱动芯片; 规格型号1: BA6208-S08-T; Datasheet: BA6208.pdf
U10 = SGM2019: SGMICRO SGM2019-2.8 300mA Input 2.5V~5.5V LDO Regulator; Part Number: 05.0010.00; Part Type: LDO; 供应商: SGMICRO; 规格型号1: SGM2019-2.8YN5G/TR; 联系人: 王哲; 手机: 18406666893; 邮箱: jayden_wang@sg-micro.com; Datasheet: SGM2019 Series.pdf
U11 = SGM2019: SII S-1339D13 300mA Input-1.5V~5.5V LDO Regulator; Part Number: 05.0037.00; Part Type: LDO; 供应商: SII; 规格型号1: S-1339D13-M5T1U3; 联系人: 张艳虹; 手机: 13611945636; 邮箱: alex.zhang@sii.co.jp; Datasheet: S1339_C5.8_00.pdf
C22 = CAP: Capacitor-100pF,+/-5%,C0G,50V-0402; Part Number: 02.0059.00; Part Type: 0402表贴普通电容; 供应商: YAGEO / Murata; 规格型号1: CC0402JRNPO9BN101 / GCM1555C1H101JA16D; 联系人: 谢苏云; 手机: 15900554174; 邮箱: susan.xie@murata.com
C26 C27 = CAP: Capacitor-3.3nF,+/-10%,X7R,50V-0402; Part Number: 02.0042.00; Part Type: 0402表贴普通电容; 供应商: YAGEO / Murata; 规格型号1: CC0402KRX7R9BB332 / GRM155R71H332KA01D; 联系人: 谢苏云; 手机: 15900554174; 邮箱: susan.xie@murata.com
D1-D9 = ESD: WILL ESD5451X-2/TR Bidirection 17.5pF Transient Voltage Suppressor; Part Number: 09.0006.00; 供应商: Will; 规格型号1: ESD5451X-2/TR; 联系人: 安志鹏; 手机: 18321800431; 邮箱: an.zhipeng@sh-willsemi.com; Datasheet: ESD5451X.pdf
J32 = MMC_SD: TF CARD SOCKET; Part Number: 10.0003.00; Part Type: TF Card; 规格型号1: TF卡座; Datasheet: TF卡座.jpg
R15 R19 = RES: Resistor-2.2K,+/-5%,1/16W-0402; Part Number: 01.0017.00; Part Type: 0402表贴普通电阻; 供应商: 厚声; 规格型号1: 0402WGJ010JTCE
R24 R26 = RES: Resistor-68K,+/-1%,1/16W-0402; Part Number: 01.0038.00; Part Type: 0402表贴高精度电阻; 供应商: 厚声; 规格型号1: 0402WGF6802TCE
U6 = CS8302: 上海智浦欣 CS8302M 3W 单声道 超低EMI 无滤波器 D类音频功放; Part Number: 06.0105.00; Part Type: 功放芯片; 供应商: 芯晶图电子; 联系人: 费军; 手机: 13808850029; 邮箱: eric.fei@shinychip.com; Datasheet: CS8302M_ch_v1.0.pdf
J6 J7 = CON_5X1: HOLY 1.5mm Pitch 5P LT SMD Connector; Part Number: 04.0007.00; Part Type: 1.5mm立贴连接器; 供应商: 深圳宏利电子; 规格型号1: 1.5mm立贴5P插座; 联系人: 谢素平; 手机: 16717558767; Datasheet: 1.5mm 立贴.pdf
J8 = HEADER_4X2: HEADER 4X2 1.27mm Pitch SMD FEMALE; Part Number: 04.0081.00; Part Type: 1.27mm双排插座; 规格型号1: 1.27mm 2X4双排SMD母座
SW2 = SW2_C: PUSHBUTTON 7.8mmX2.5mm 2Pin; Part Number: 04.1004.00; Part Type: 按键; Datasheet: 侧键ST-1112A-5万次.PDF
U12 = ULN2803A-QFN203PDB3: 重庆中科芯亿达 ULN2803A Darlington transistor array Motor Driver; Part Number: 06.0003.00; Part Type: 驱动芯片; Datasheet: ULN2803A-QFN203PDB3.pdf

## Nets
2V8: C37.1 R37.1 U10.5(VOUT)
AGND: C32.1 C33.1 C37.2 C40.2 C41.2 C42.2 C52.2 R39.1 U7.B1(AGND_1) U7.B7(AGND_2)
AVDD2V8: C40.1 C41.1 C42.1 R37.2 U7.A1(AVDD_1) U7.A7(AVDD_2)
DVDD1V2OUT: C79.1 C175.1 U4.T14(DVDD1V2OUT)
DVDD1V3: C45.1 C46.1 C47.1 R27.1 U7.C1(DVDD_1) U7.D6(DVDD_2) U11.5(VOUT)
GND: C1.2 C2.2 C3.2 C4.2 C7.2 C8.2 C9.2 C10.2 C12.2 C13.2 C14.2 C16.2 C17.1 C18.2 C20.2 C21.1 C23.2 C24.2 C25.1 C26.2 C28.2 C29.2 C30.2 C31.2 C34.2 C35.1 C36.1 C38.2 C39.2 C43.2 C44.2 C45.2 C46.2 C47.2 C48.2 C49.2 C50.2 C51.2 C53.2 C54.2 C58.2 C61.2 C63.2 C65.2 C66.2 C67.2 C68.2 C69.2 C72.2 C73.2 C74.2 C75.2 C76.2 C77.2 C79.2 C84.2 C86.2 C88.2 C89.2 C90.1 C96.2 C97.1 C140.2 C143.2 C144.2 C146.2 C147.2 C148.2 C149.2 C175.2 C176.2 C187.2 C189.2 C203.2 C206.2 C212.2 C213.2 C214.2 C215.2 C216.2 C217.2 C218.2 C231.2 C232.2 C233.2 C234.2 C238.2 C239.2 C240.2 C241.2 C244.1 C248.2 C250.2 C255.2 D1.1(ANODE) D2.2(CATHODE) D3.2(CATHODE) D4.2(CATHODE) D5.2(CATHODE) D6.2(CATHODE) D7.2(CATHODE) D8.2(CATHODE) D9.2(CATHODE) HOLE1.1(TP) HOLE2.1(TP) HOLE3.1(TP) HOLE4.1(TP) J1.3(S1) J1.4(S2) J2.3(S1) J2.4(S2) J3.3 J3.4 J3.7 J3.10 J3.15(S1) J3.16(S2) J4.3(S1) J4.4(S2) J5.1(HOL1) J5.2(HOL2) J6.6(S1) J6.7(S2) J7.6(S1) J7.7(S2) J8.7 J9.1 J9.2 J32.6(VSS2) J32.10(GND_2) J32.11(GND_1) J32.12(PAD1) J32.13(PAD2) L5.2 Q3.2(EMITTER) R4.1 R6.2 R9.1 R13.1 R14.2 R15.2 R21.2 R28.2 R29.2 R36.1 R39.2 R42.2 R43.2 R44.1 R45.1 R46.1 R47.1 R48.1 R49.1 R50.2 R58.1 R61.1 R71.1 R75.2 R312.2 R315.2 R345.2 R347.1 SW2.1 SW2.3 SW2.4 U1.2(GND) U2.2(GND) U3.2(GND) U4.C9(DDRPLL_VSSA) U4.G5(PLL_AVSS) U4.G6(VSS1) U4.G7(VSS2) U4.G8(VSS3) U4.G9(VSS4) U4.G10(VSS5) U4.G11(VSS6) U4.G12(VSS7) U4.G13(VSS8) U4.J6(VSS9) U4.J7(VSS10) U4.J8(VSS11) U4.J9(VSS12) U4.J10(VSS13) U4.J11(VSS14) U4.J12(VSS15) U4.K6(VSS16) U4.K7(VSS17) U4.K8(VSS18) U4.K9(VSS19) U4.K10(VSS20) U4.K11(VSS21) U4.K12(VSS22) U4.L6(VSS23) U4.L7(VSS24) U4.L8(VSS25) U4.L9(VSS26) U4.L10(VSS27) U4.L11(VSS28) U4.L12(VSS29) U4.M7(VSS30) U4.M8(VSS31) U4.M9(VSS32) U4.M10(VSS33) U4.M11(VSS34) U4.M12(VSS35) U4.M13(VSS36) U4.N5(CSI_VSSA) U4.N12(VSS37) U4.N13(SADC_AGND) U4.N15(SADC_VIN3) U4.P4(CODEC_AVSS) U4.P16(SADC_VIN2) U4.R17(SADC_VIN1) U5.2(GND) U6.7(GND) U7.C3(DOGND_1) U7.D2(DOGND_2) U7.E6(DOGND_3) U7.F6(DOGND_4) U9.3(GND0) U9.7(GND1) U10.2(GND) U11.2(GND) U12.8(GND) U12.21(E_PAD) U13.4(GND) U13.9(E-PAD) U14.1(GND1) U14.6(GND2) Y1.2 Y1.4
VCC_5V: C1.1 C8.1 C9.1 C13.1 C18.1 C28.1 C29.1 C30.1 C31.1 C36.2 C51.1 C58.1 C77.1 J3.1 J3.2 J6.1 J7.1 J8.1 J8.2 R1.1 R2.1 R7.1 R10.1 TP4.1 TP13.1 U1.4(IN) U2.4(IN) U3.4(IN) U5.4(IN) U6.6(VDD) U9.1(VCC) U12.9(COM)
VDDMSC0: C146.1 C147.1 D2.1(ANODE) J32.4(VDD) Q1.3(DRAIN) R209.1 R210.1 R211.1 R212.1 R213.1
A0+: J6.2 TP12.1 U12.14(4C)
A0-: J6.4 TP10.1 U12.16(2C)
A1+: J7.2 TP17.1 U12.10(8C)
A1-: J7.4 TP15.1 U12.12(6C)
ADC_AVDD: FB1.2 U4.N16(SADC_VREFP) U4.N17(SADC_AVDD)
B0+: J6.3 TP11.1 U12.15(3C)
B0-: J6.5 TP9.1 U12.17(1C)
B1+: J7.3 TP16.1 U12.11(7C)
B1-: J7.5 TP14.1 U12.13(5C)
BOOTSEL0: R59.1 U4.A9(BOOT_SEL0_PC00)
BOOTSEL1: R60.1 R61.2 U4.B9(BOOT_SEL1_PC01)
CODEC_AVDD: C53.1 C54.1 FB7.2 U4.R1(CODEC_AVDD)
CSI_CLKN: U4.M2(CSI_CLKN_DVP_D4) U7.E4(MCN)
CSI_CLKP: U4.L3(CSI_CLKP_DVP_D5) U7.F4(MCP)
CSI_DATAN0: U4.L2(CSI_DATAN0_DVP_D0) U7.F5(MDN0)
CSI_DATAN1: U4.N1(CSI_DATAN1_DVP_D2) U7.E3(MDN1)
CSI_DATAP0: U4.L1(CSI_DATAP0_DVP_D1) U7.E5(MDP0)
CSI_DATAP1: U4.M3(CSI_DATAP1_DVP_D3) U7.F3(MDP1)
DDR_VREF: C244.2 R346.1 R347.2 U4.E5(DDR_VREF)
DOVDD1V8: C11.1 C12.1 C34.1 C43.1 C44.1 C63.1 C88.1 C140.1 C143.1 C187.1 C248.1 C250.1 C255.1 FB1.1 FB7.1 L3.2 R8.2 R30.1 R32.1 R33.1 R34.1 R35.1 R343.1 TP2.1 U4.B8(DDRPLL_VCCA) U4.D3(PLL_AVDD) U4.K2(VDDIO18_2) U4.K3(CSI_VCCA18) U4.L17(VDDIO_RTC) U4.N11(VDDIO18_1) U4.T3(USB_AVD18) U7.D4(DOVDD_1) U7.E2(DOVDD_2)
EFUSE_AVDD: R14.1 U4.D4(EFUSE_AVDD)
EN_DLDO: R50.1 R51.1 U4.U15(EN_DLDO)
EXCLKI: C21.2 R17.2 U4.C1(EXCLK_XIN) Y1.1
EXCLKO: C25.2 R17.1 U4.D2(EXCLK_XOUT) Y1.3
FACTORY_RESET: C72.1 D1.2(CATHODE) R53.2 SW2.2 U4.C12(DMIC_DAT1_UART4_RXD_PB30)
G: J8.8 R56.1
HPOUTL: C27.2 U4.T1(HPOUTL)
IRCUTN: R29.1 U4.E17(MSC1_D1_PB18) U9.5(BIN)
IRCUTP: R28.1 U4.E16(MSC1_D0_PB17) U9.8(AIN)
IRLED_EN: R55.1 TP19.1 U4.C8(SMB1_SCK_PC20)
LDR1: C73.1 J8.6 R25.2 R58.2 TP20.1
LED_G: R56.2 TP21.1 U4.C6(SMB2_SCK_PC09)
LED_R: R54.1 U4.C5(I2S_DAC_MCLK_PC11)
LINK/ACT: J3.11 R99.1 TP5.1
M0: R42.1 U4.A3(SSI_SLV_CE0_I2S_DAC_LRCK_PC16) U12.19(1B)
M1: R43.1 U4.B3(SSI_SLV_DT_I2S_SDTO_PC17) U12.20(2B)
M2: R44.2 U4.B4(SSI_SLV_CLK_I2S_DAC_BCLK_PC15) U12.1(3B)
M3: R45.2 U4.B5(SSI_SLV_DR_I2S_SDTI_PC18) U12.2(4B)
M4: R46.2 U4.A5(I2S_ADC_MCLK_PC12) U12.3(5B)
M5: R47.2 U4.B6(SMB2_SDA_PC08) U12.4(6B)
M6: R48.2 U4.B7(I2S_ADC_BCLK_PC13) U12.5(7B)
M7: R49.2 U4.A7(SMB1_SDA_PC19) U12.6(8B)
MCLK: R57.2 U4.E1(SA1_DVP_MCLK_PA15)
MICBIAS: C68.1 C69.1 R20.2 U4.P3(MICBIAS)
MICNL: C22.1 C71.2 J1.1 R15.1 R18.1
MICPL: C22.2 C70.2 J1.2 R18.2 R19.2
MINNL: C71.1 U4.P2(MICNL)
MINPL: C70.1 U4.N3(MICPL)
MSC0_CLK_PB04: D3.1(ANODE) J32.5(CLK) R207.1 TP48.1
MSC0_CMD_PB05: D4.1(ANODE) J32.3(CMD) R210.2 TP44.1 U4.G17(MSC0_CMD_PB05)
MSC0_D0_PB00: D5.1(ANODE) J32.7(DAT0) R209.2 TP43.1 U4.H16(MSC0_D0_PB00)
MSC0_D1_PB01: D6.1(ANODE) J32.8(DAT1) R211.2 TP45.1 U4.J15(MSC0_D1_PB01)
MSC0_D2_PB02: D7.1(ANODE) J32.1(DAT2) R212.2 TP46.1 U4.G15(MSC0_D2_PB02)
MSC0_D3_PB03: D8.1(ANODE) J32.2(DAT3) R213.2 TP47.1 U4.G16(MSC0_D3_PB03)
MVDD: C39.1 R27.2 U7.B5(MVDD)
PHY_AVDDL_REG: C74.1 C76.1 U4.R16(AVDDL_REG)
PHY_LED0: R99.2 U4.R13(LED0)
PHY_LED1: R100.2 U4.R15(LED1)
PHY_RST: C176.1 R52.1 U4.A11(DMIC_CLK_SMB2_SCK_PB28) U4.T13(PHY_RST)
POR_CTRL: R343.2 U4.K16(POR_CTL)
PWDN_PA19: R33.2 U4.E2(WAIT_PA19) U7.A4(PWDNB)
RD_N: J3.5 U4.U17(RD_N)
RD_P: J3.6 U4.T17(RD_P)
RX_DV: R313.1 U4.P14(RX_DV)
RXD3: R314.1 R315.1 U4.R14(RXD3)
RZQ: R75.1 U4.D9(RZQ)
SD0_CD_N: C150.2 D9.1(ANODE) J32.9(CD) Q1.1(GATE) R214.2 U4.C10(SMB1_SCK_UART3_RXD_PB26)
SENSOR_MCLK: R57.1 U7.C2(MCLK)
SENSOR_RESET: C35.2 R34.2 U4.E3(SA2_PA18) U7.C4(RESETB)
SFC_CS_N: R12.1 U4.T4(SFC0_CE_PA28) U13.1(~{CS})
SFC_SCLK: U4.R6(SFC0_CLK_PA27) U13.6(SCLK)
SFC_SIO0: U4.U5(SFC0_DT_IO0_PA23) U13.5(SI/SIO0)
SFC_SIO1: U4.R5(SFC0_DR_IO1_PA24) U13.2(SO/SIO1)
SFC_SIO2: U4.T5(SFC0_WP_IO2_PA26) U13.3(~{WP}/SIO2)
SFC_SIO3: U4.T6(SFC0_HOLD_IO3_PA25) U13.7(~{HOLD}/SIO3)
SID: R35.2 R36.2 U7.A5(SID)
SMB0_SCK: R30.2 U4.J4(SD7_SMB0_SCK_PA13) U7.A3(SCL)
SMB0_SDA: R32.2 U4.J1(SD6_SMB0_SDA_PA12) U7.B3(SDA)
SOC_0V8: C2.1 C4.1 C6.2 C48.1 C61.1 C86.1 C90.2 C203.1 C206.1 C212.1 C213.1 C214.1 C215.1 C216.1 C217.1 C218.1 L1.2 R5.2 TP25.1 U4.H5(VDD1) U4.H6(VDD2) U4.H7(VDD3) U4.H8(VDD4) U4.H9(VDD5) U4.H10(VDD6) U4.H11(VDD7) U4.H12(VDD8) U4.H13(VDD9) U4.J5(VDD10) U4.J13(VDD11) U4.K5(VDD12) U4.K13(VDD13) U4.L5(VDD14) U4.L15(VDD_RTC) U4.M5(VDD15) U4.M6(VDD16) U4.N2(CSI_VCCA08) U4.N6(VDD17) U4.N7(VDD18) U4.N8(VDD19) U4.N9(VDD20) U4.N10(VDD21) U4.R4(USB_AVD08)
SOC_3V3: C5.1 C7.1 C17.2 C49.1 C65.1 C75.1 C91.2 C96.1 C144.1 C148.1 C149.1 C150.1 C189.1 L2.2 Q1.2(SOURCE) Q2.2(SOURCE) R3.2 R12.2 R16.2 R23.2 R38.1 R40.1 R51.2 R52.2 R53.1 R59.2 R60.2 R68.1 R69.2 R214.1 R313.2 R314.2 TP1.1 U4.C4(VDDIO2) U4.J14(VDDIO1_2) U4.P9(VDDIO1_1) U4.R3(USB_AVD33) U10.1(VIN) U11.1(VIN) U13.8(VCC)
SOC_DDR: C15.1 C16.1 C231.1 C232.1 C233.1 C234.1 C238.1 C239.1 C240.1 C241.1 L4.2 R11.2 R346.2 TP3.1 U4.E6(VDDMEM1) U4.E7(VDDMEM2) U4.E8(VDDMEM3) U4.E9(VDDMEM4) U4.E10(VDDMEM5) U4.E11(VDDMEM6) U4.E12(VDDMEM7) U4.F5(DDRVDD1) U4.F6(DDRVDD2) U4.F7(DDRVDD3) U4.F8(DDRVDD4) U4.F9(DDRVDD5) U4.F10(DDRVDD6) U4.F11(DDRVDD7) U4.F12(DDRVDD8)
SPEAK_EN_PB31: R22.1 U4.B10(GPIO_PB31)
SPEED: J3.12 R100.1 TP6.1
TD_N: J3.8 U4.U16(TD_N)
TD_P: J3.9 U4.T16(TD_P)
UART1_RXD: J3.13 U4.F16(UART1_RXD_PB24)
UART1_TXD: J3.14 U4.F15(UART1_TXD_PB23)
USB_DM: U4.U1(USB0PN) U14.3(D-)
USB_DP: U4.T2(USB0PP) U14.2(D+)
VCM: C66.1 C67.1 U4.R2(VCM)
VOTP: TP24.1 U7.E7(VOTP)
WIFI_3V3: C84.1 C89.1 Q2.3(DRAIN) R68.2 U14.4(3V3)
WIFI_PWR_EN: R70.1 U4.C11(SMB1_SDA_UART3_TXD_PB25)
ZQ: R345.1 U4.F13(DDR_ZQ)
N16068033: J4.2 U9.4(AOUT)
N16068049: J4.1 U9.2(BOUT)
N16494121: C83.1 C97.2 U14.5(ANT1)
N16494125: C83.2 J9.3 L5.1
N16658117: C91.1 Q2.1(GATE) Q3.3(COLLECTOR) R69.1
N16658257: Q3.1(BASE) R70.2 R71.2
N16680846: C38.1 R38.2 U10.3(EN)
N16681558: C50.1 R40.2 U11.3(EN)
N16842331: J8.3 R54.2 TP18.1
N17912916: C5.2 R3.1 R4.2 U1.5(FB)
N17912932: L2.1 U1.3(LX)
N17913000: C3.1 R1.2 U1.1(EN)
N17913512: C10.1 R2.2 U2.1(EN)
N17913867: C14.1 R7.2 U3.1(EN)
N17913916: L3.1 U3.3(LX)
N17913918: C11.2 R8.1 R9.2 U3.5(FB)
N17914253: C20.1 R10.2 U5.1(EN)
N17914314: C15.2 R11.1 R13.2 U5.5(FB)
N17914320: L4.1 U5.3(LX)
N17923584: C23.1 C24.1 R19.1 R20.1
N17923959: R21.1 R22.2 U6.1(/SD)
N17923983: J2.2 U6.5(VO+)
N17923995: J2.1 U6.8(VO-)
N17924016: R26.1 U6.4(-IN)
N17924026: C27.1 R26.2
N17924036: C26.1 R24.2
N17924072: R24.1 U6.3(+IN)
N17926744: C32.2 U7.D7(TXLOW)
N17926746: C33.2 U7.F7(VREF)
N17992613: C6.1 R5.1 R6.1 U2.5(FB)
N17994204: L1.1 U2.3(LX)
N18040120: R312.1 U4.T15(RBIAS)
N18040755: R207.2 U4.H15(MSC0_CLK_PB04)
N18061971: C52.1 U10.4(BP/FB)
N18083960: R16.1 U4.T10(GMAC_MDIO_SMB2_SCK_PB11)
N18093878: R23.1 U4.R10(GMAC_MDCK_SMB2_SDA_PB10)
N18145476: J8.4 R55.2
N18146133: R25.1 U4.P15(SADC_VIN0)

Not connected (* = marked no-connect by the designer): J8 5*; U4 A1(MSC1_CLK_PC02)* A2(MSC1_D1_PC05)* A13(SLCD_TE_PWM4_PD09)* A15(SLCD_D0_UART3_TXD_PD00)* A16(SLCD_D2_UART4_TXD_PD02)* A17(SLCD_D4_UART5_TXD_PD04)* B1(MSC1_D3_PC07)* B2(MSC1_D0_PC04)* B11(DRV_VBUS_SMB2_SDA_PB27)* B12(DMIC_DAT0_UART4_TXD_PB29)* B13(SLCD_CS_PWM5_PD10)* B14(SLCD_WR_PD08)* B15(SLCD_D1_UART3_RXD_PD01)* B16(SLCD_D5_UART5_RXD_PD05)* B17(SLCD_D6_SMB1_SDA_PD06)* C2(MSC1_D2_PC06)* C3(MSC1_CMD_PC03)* C7(I2S_ADC_LRCK_PC14)* C13(SLCD_DC_PWM6_PD11)* C14(SLCD_RDY_PWM7_PD12)* C15(SLCD_D3_UART4_RXD_PD03)* C16(SLCD_D7_SMB1_SCK_PD07)* C17(MSC1_D2_TMS_PB21)* D14(TRST_)* D15(MSC1_D3_PB22)* D16(MSC1_CMD_PB19)* E15(MSC1_CLK_TCK_PB20)* F2(NC_2)* F3(SA0_DVP_PCLK__PA14)* G1(SD2_DVP_D8_PA08)* G2(SD3_DVP_D9_PA09)* G3(NC_1)* H2(SD0_DVP_D6_PA06)* H3(SD1_DVP_D7_PA07)* J2(CS2_DVP_HSYNC_PA16)* J3(RD_DVP_VSYNC_PA17)* J16(RST_OUT)* J17(WKUP_PD31)* K15(PWRON)* L13(TEST_TE)* L16(PPRST_)* M15(OSC32_XO)* M16(OSC32_XI)* R7(SFC1_CE_PA29)* R8(SFC1_DT_IO0_PA20)* R9(SFC1_HOLD_IO3_PA31)* R11(GMAC_TXD0_PWM4_PB13)* R12(GMAC_RXD1_PWM7_PB16)* T7(SFC1_DR_IO1_PA21)* T8(SFC1_CLK_PA22)* T9(GMAC_PHY_CLK_PB07)* T11(GMAC_TXD1_PWM5_PB14)* T12(GMAC_TXCLK_PB06)* U2(USB0ID)* U3(VBUS)* U7(SFC1_WP_IO2_PA30)* U9(GMAC_RXDV_PWM3_PB09)* U11(GMAC_TXEN_PWM2_PB08)* U13(GMAC_RXD0_PWM6_PB15)*; U6 2(NC)*; U7 A2(NC_1)* A6(NC_2)* B2(NC_3)* B6(FSYNC)* C5(NC_4)* C6(NC_5)* C7(NC_6)* D1(NC_7)* D3(NC_8)* D5(NC_9)* E1(NC_10)* F1(NC_11)* F2(NC_12)*; U9 6(NC)*; U11 4(BP/FB)*; U12 7(NC1)* 18(NC2)*

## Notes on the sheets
sheet 1
- USB WIFI
- NC
- NC
- Supported other wifi module:
- BL-M8188FU3
- BL-M8188EU1
- BL-7601MU2
- INGENIC SEMICONDUCTOR CO.,LTD
sheet 2
- MOTOR_RST_LED
- MOTOR
- MOTOR1：
- horizontal
- MOTOR2：
- vertical
- NC
- Assembly for debug
- LED
- NC
- NC
- NC
- NC
- Assembly for ESD
- INGENIC SEMICONDUCTOR CO.,LTD
- Reserverd for hardware light sensor
sheet 3
- SENSOR
- IRCUT
- CIS
- NC
- 7bit I2C Address (floating forbidden)
- NC
- 0  0X52 (default)
- 1  0X20
- Sensor power
- GC4663 power on sequence：
  DOVDD -->DVDD --> AVDD
- INGENIC SEMICONDUCTOR CO.,LTD
sheet 4
- MARK_C90_MAIN
- INGENIC
- Schematic Revision 1.2
- Title
- Page
- COVER
- 1
- SYSTEM-ARCHITECTURE
- 2
- POWER-SUPPLY
- 3
- T41_POWER
- 4
- T41_SYS_APeripheral
- 5
- T41_INTERFACE_1
- 6
- T41_INTERFACE_2
- 7
- USB_WIFI
- 8
- ETH_PHY
- 9
- SENSOR
- 10
- SD_AUDIO
- 11
- MOTOR_RST_LED
- 12
- REVISION-HISTORY
- 13
sheet 5
- MIC
- CODEC
- Transformer
- RJ45
- ETH_PHY
- SPEAKER
- SD Card
- MSC0
- FLASH
- SFC
- T41
- IRCUT,MOTOR
- GPIO
- LDR
- ADC
- USB2.0
- USB WIFI
- SMB0
- DEBUG
- UART1
- MIPI
- MIPI
- BOOT
- CLK
- RST
- 24M
- Reset
- BOOT
- CRY
- Reset
- SOC_DDR
- DCDC
- Imax:1.5A
- DOVDD18
- SOC_0V8
- DCDC
- Imax:2A
- SOC_1V8
- DCDC
- Imax:1.5A
- VCC_5V
- SOC_3V3
- USB
- DCDC
- Imax:1.5A
- AVDD28
- LDO
- Imax:300mA
- DVDD13
- LDO
- Imax:300mA
sheet 6
- POWER-SUPPLY
- 3.3V/1.5A
- VDD Core 0.8V/2A
- 0.6V
- 0.6V
- Note: Compatible with ETA3486
- VOUT=(1+150K/33.2K)*0.6=3.3V
- VOUT=(1+100K/300K)*0.6=0.8V
- VCC_DDR/1.5A
- 1.8V/1.5A
- 0.6V
- 0.6V
- Note: Compatible with ETA3486
- Note: Compatible with ETA3486
- VCC_1V8=(1+200K/100K)*0.6=1.8V
- VCC_DDR=(1+200K/100K)*0.6=1.8V for DDR2
- VCC_DDR=(1+150K/100K)*0.6=1.5V for DDR2L or DDR3
- VCC_DDR=(1+150K/120K)*0.6=1.35V for DDR3L
- √
- NC
- NC
- NC
- NC
- Mechanical Hole
sheet 7
- T41_POWER
sheet 8
- T41_SYS_APeripheral
- POR CTRL
- 1    POR
- 0    PPRST
- BOOTSEL
- NC
- BOOT_SEL1
- BOOT_SEL0
- BOOT FROM
- MMC/SD boot@MSC0(MMC/SD use GPIO Port B.
  MSC1 use GPIO Port C)
- 0
- 0
- 1
- 0
- UART boot @ CS2(Ymodem@115200/9600)
- 1
- 1
- USB boot @USB2.0 device, EXTCLK=24MHz
- 0
- 1
- SFC boot @ CS4(SPI boot)
- NAND
  FLASH
- CLK
- NC
sheet 9
- T41_INTERFACE_1
- NC
- NC
sheet 10
- T41_INTERFACE_2
sheet 11
- SD_AUDIO
- SD CARD
- NC
- Assembly for ESD
- MICL
- NC
- NC
- -
- +
sheet 12
- ETH_PHY
sheet 13
- Date
- Revision
- Change
- July 01 2022
- Rev1.0
- 1. First Revision
- Sep 20 2022
- Rev1.1
- 1. PHY_RST Changed From PB19 To PB28.
- 2. SYS_RESET Changed From PC14 To PB30.
- 1.T41.G3&F2 Ball  Change to NC.
- Nov 01 2022
- Rev1.2
- 2.ADC Channel Series 4.7R Resistor.
- 3.Update T41 package
